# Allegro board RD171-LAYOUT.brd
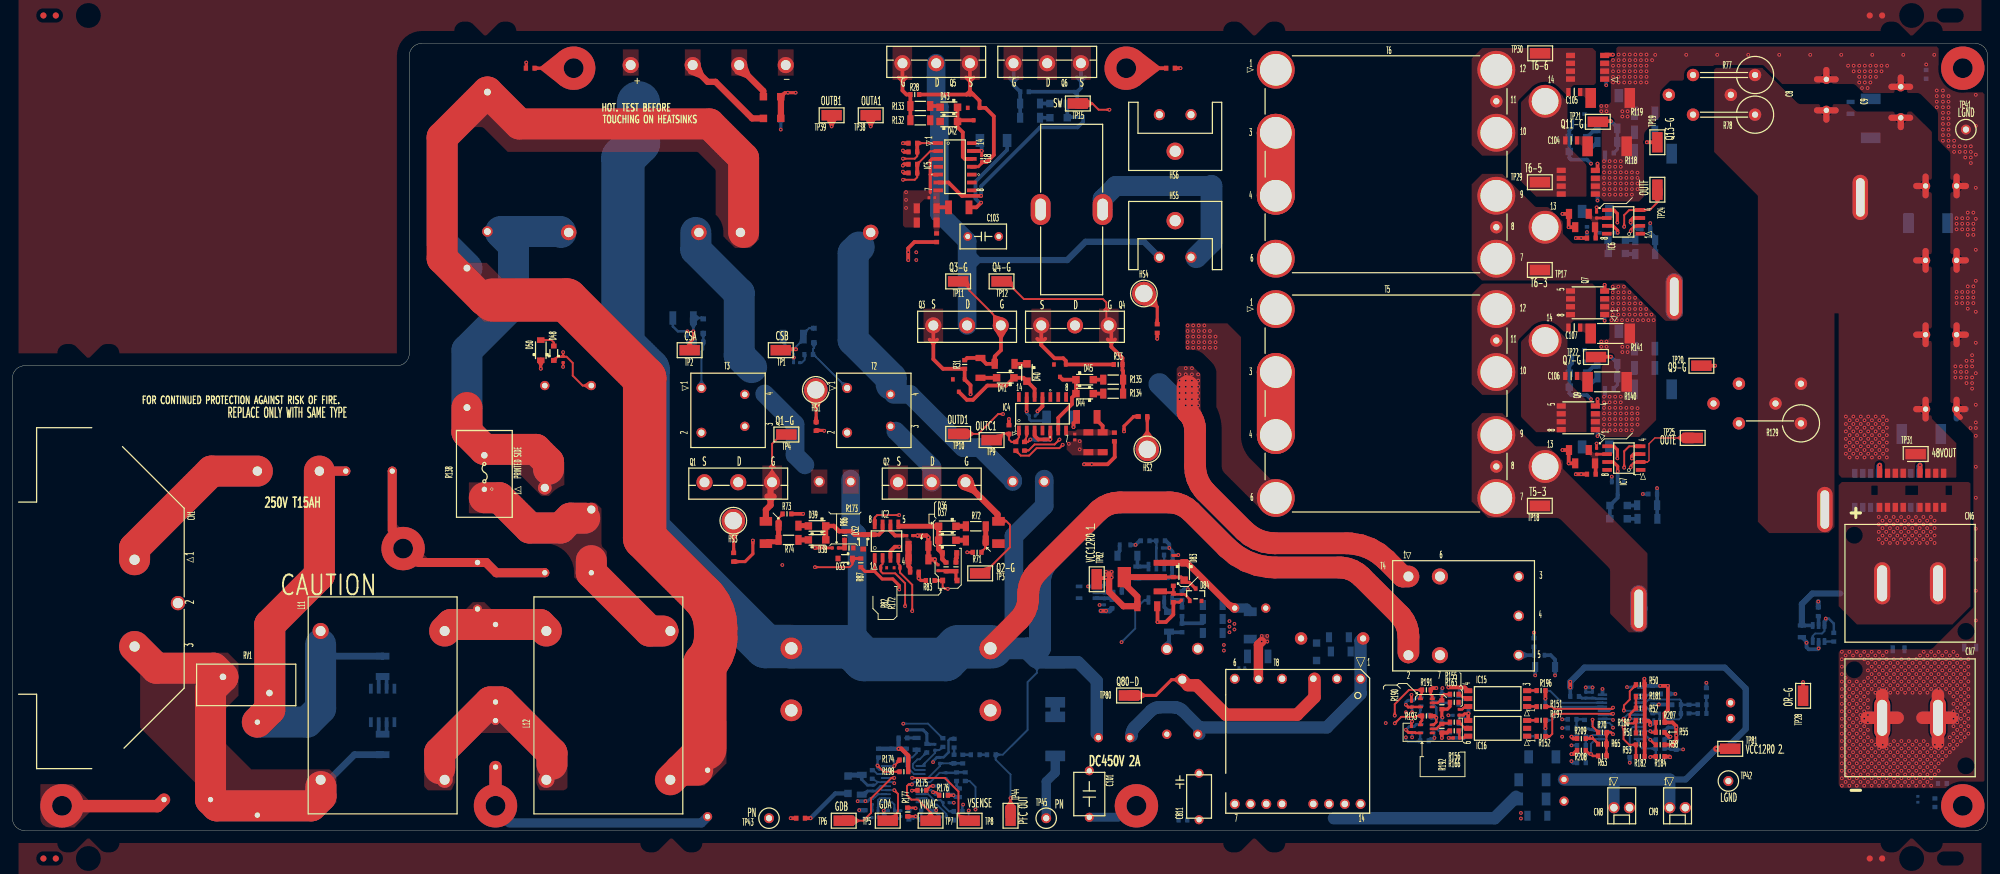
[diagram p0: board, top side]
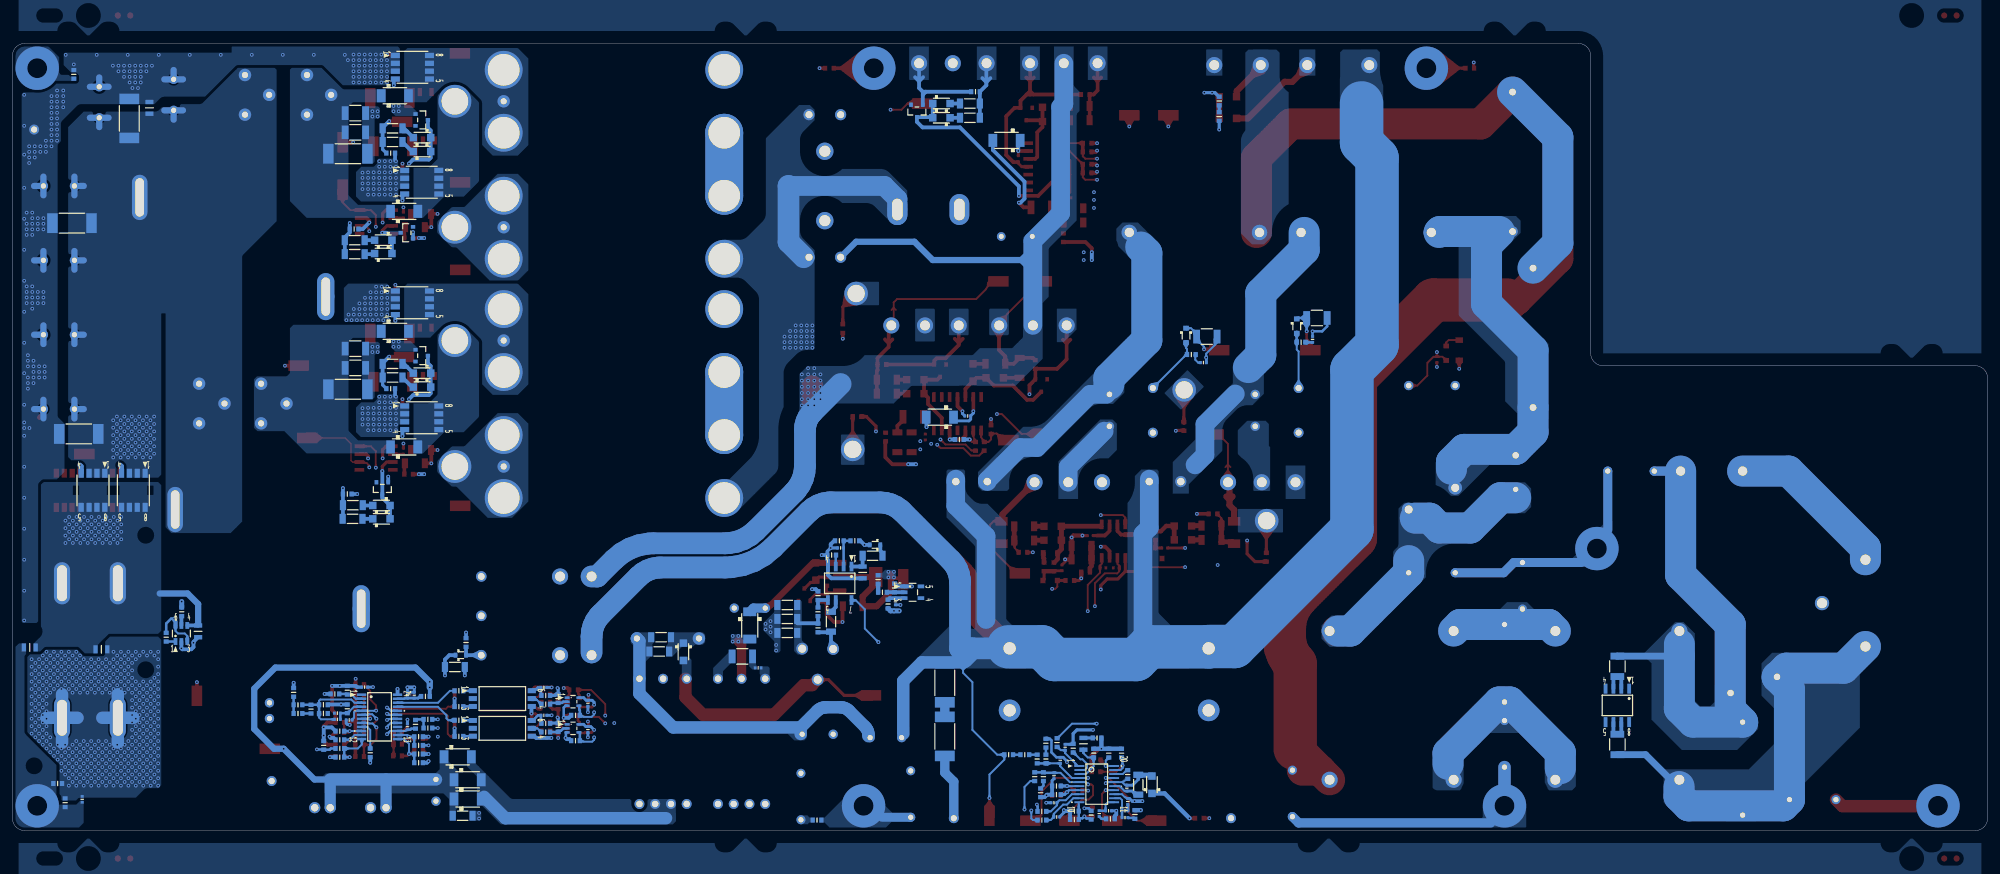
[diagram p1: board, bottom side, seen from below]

Outline 318.5 x 127 mm; copper layers: TOP, CONDUCTIVE2, CONDUCTIVE3, CONDUCTIVE4, CONDUCTIVE5, BOTTOM. Coordinates in mm from the lower left corner of the outline.
Outline path: 0,73 0.03,73.35 0.12,73.68 0.27,74 0.47,74.29 0.71,74.53 1,74.73 1.32,74.88 1.65,74.97 2,75 62,75 62.35,75.03 62.68,75.12 63,75.27 63.29,75.47 63.53,75.71 63.73,76 63.88,76.32 63.97,76.65 64,77 64,125 64.03,125.35 64.12,125.68 64.27,126 64.47,126.29 64.71,126.53 65,126.73 65.32,126.88 65.65,126.97 66,127 316.5,127 316.85,126.97 317.18,126.88 317.5,126.73 317.79,126.53 318.03,126.29 318.23,126 318.38,125.68 318.47,125.35 318.5,125 318.5,2 318.47,1.65 318.38,1.32 318.23,1 318.03,0.71 317.79,0.47 317.5,0.27 317.18,0.12 316.85,0.03 316.5,0 2,0 1.65,0.03 1.32,0.12 1,0.27 0.71,0.47 0.47,0.71 0.27,1 0.12,1.32 0.03,1.65 0,2 0,73

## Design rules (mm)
constraint set DEFAULT: 

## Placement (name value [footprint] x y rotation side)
C1  -  [AC_I_DIA_30_RB]  157.7 24.4 270 top
C2  -  [AC_I_DIA_10_CC]  311 104 0 top
C3  -  [AC_I_DIA_10_CC]  311 92 0 top
C4  -  [AC_I_DIA_10_CC]  311 80 0 top
C5  -  [AC_I_DIA_10_CC]  311 68 0 top
C7  -  [AC_I_DIA_30_RB]  125.6 24.4 270 top
C8  -  [AC_I_DIA_10_CC]  292.5 118.7 90 top
C9  -  [AC_I_DIA_10_CC]  304.5 117.5 90 top
C18  -  [CHIP1005_GS_2]  156.3 108.4 90 top
C19  -  [CHIP1005_GS_2]  164.45 66.9 180 bottom
C20  -  [CHIP1608_GS_1]  270.35 19.6 270 bottom
C21  -  [CHIP1005_GS_2]  266.1 18.95 180 bottom
C22  -  [CHIP1005_GS_2]  266.1 17.95 180 bottom
C23  -  [CHIP1005_GS_2]  253.7 21.85 270 bottom
C24  -  [CHIP1005_GS_2]  254.8 21.85 270 bottom
C25  -  [CHIP1005_GS_2]  264.2 17.85 180 bottom
C26  -  [CHIP1005_GS_2]  254.8 16.75 270 bottom
C27  -  [CHIP3225_GS_1]  263.2 115.75 0 bottom
C30  -  [C_I_LE474_M_OK]  39.5 10 90 top
C31  -  [C_I_DE2_KY____M_F_MU_1]  77.9 14 90 top
C32  -  [C_I_DE2_KY____M_F_MU_1]  75 39.5 270 top
C33  -  [C_I_890324026034CS_W_1]  76.6 107.9 270 top
C34  -  [CHIP1005_GS_2]  126.45 75.5 0 bottom
C35  -  [CHIP1005_GS_2]  149.25 42.4 270 top
C36  -  [CHIP1005_GS_2]  108.85 79.25 270 bottom
C37  -  [CHIP1005_GS_2]  132.7 45.6 0 top
C38  -  [CHIP1005_GS_2]  150.55 8.85 90 bottom
C39  -  [CHIP1005_GS_2]  149.55 11.35 270 bottom
C40  -  [CHIP1608_GS_1]  144.15 12.5 270 bottom
C41  -  [CHIP2012_GS_1]  145.8 14 270 bottom
C42  -  [CHIP1005_GS_2]  138.65 4.7 90 bottom
C43  -  [CHIP1005_GS_2]  139.1 3.2 0 bottom
C44  -  [CHIP1005_GS_2]  139.1 2.1 0 bottom
C45  -  [CHIP1005_GS_2]  141.75 3.2 0 bottom
C46  -  [CHIP1005_GS_2]  143.25 2.75 90 bottom
C47  -  [CHIP1005_GS_2]  138.8 6.85 270 bottom
C48  -  [CHIP3216_GS_1]  136.95 7.4 270 bottom
C49  -  [CHIP1608_GS_1]  138.65 9.05 90 bottom
C50  -  [CHIP1005_GS_2]  148.75 13.45 270 bottom
C51  -  [CHIP3225_GS_1]  263.2 77.75 0 bottom
C52  -  [C_I_LE224_M_OK]  77.9 27 90 top
C53  -  [CHIP1608_GS_1]  145.2 107.5 0 top
C54  -  [CHIP1608_GS_1]  145.2 110.9 0 top
C55  -  [CHIP1005_GS_2]  148.28 102.1 0 top
C56  -  [CHIP1608_GS_1]  165.8 63.1 180 bottom
C57  -  [CHIP1608_GS_1]  160.7 64.7 270 top
C58  -  [CHIP1005_GS_2]  171.3 63.5 90 top
C59  -  [CHIP1608_GS_1]  293.7 31.2 90 bottom
C60  -  [CHIP1005_GS_2]  255.45 61.2 270 top
C61  -  [CHIP1005_GS_2]  255.45 99.3 270 top
C62  -  [CHIP1005_GS_2]  144.7 47.6 180 top
C63  -  [C_I_DE2_KY____M_F_MU_1]  112.1 6 90 top
C64  -  [C_I_DE2_KY____M_F_MU_1]  89.6 41.6 0 top
C65  -  [C_I_890324026034CS_W_1]  73.3 79.5 270 top
C66  -  [CHIP1608_GS_1]  176.25 39.15 270 bottom
C67  -  [CHIP1005_GS_2]  176.1 36.9 90 bottom
C68  -  [CHIP3225_GS_1]  263.2 112.65 0 bottom
C69  -  [CHIP3225_GS_1]  263.2 74.65 0 bottom
C70  -  [CHIP1005_GS_2]  88.8 76 90 top
C71  -  [CHIP1005_GS_2]  232.8 23.1 0 bottom
C72  -  [CHIP1005_GS_2]  232.8 18.6 0 bottom
C73  -  [CHIP1005_GS_2]  233.3 19.1 90 top
C74  -  [CHIP1005_GS_2]  232.85 14.95 0 top
C75  -  [CHIP1005_GS_2]  150.55 4.5 180 bottom
C76  -  [CHIP1005_GS_2]  150.1 2.2 0 bottom
C77  -  [CHIP1608_GS_1]  147.25 3.15 180 bottom
C78  -  [C_I_DE2_KY____M_F_MU]  57.5 58 180 top
C79  -  [C_I_DE2_KY____M_F_MU]  28.2 5 0 top
C80  -  [CHIP1005_GS_2]  142.65 42.4 0 top
C81  -  [CHIP1005_GS_2]  140.5 42.4 180 top
C82  -  [CHIP3216_GS_1]  146.1 45.95 180 top
C83  -  [CHIP3216_GS_1]  146.1 43.75 180 top
C84  -  [CHIP3216_GS_1]  173.5 62.65 90 top
C85  -  [CHIP3216_GS_1]  175.8 62.65 90 top
C86  -  [CHIP3216_GS_1]  147.43 98.1 0 top
C87  -  [CHIP3216_GS_1]  147.43 100.4 0 top
C88  -  [CHIP3216_GS_1]  252.6 99.5 0 top
C89  -  [CHIP3216_GS_1]  253.6 97.35 0 top
C90  -  [CHIP3216_GS_1]  253.6 59.25 0 top
C91  -  [CHIP3216_GS_1]  252.6 61.4 0 top
C92  -  [CHIP2012_GS_1]  304.15 29.25 0 bottom
C93  -  [CHIP2012_GS_1]  315.7 29.55 180 bottom
C94  -  [CHIP1005_GS_2]  307.25 5.05 270 bottom
C95  -  [CHIP1005_GS_2]  225.7 20.55 90 bottom
C96  -  [CHIP1005_GS_2]  225.7 16.3 90 bottom
C97  -  [CHIP1005_GS_2]  225.6 20.4 270 top
C98  -  [CHIP1005_GS_2]  225.6 16.3 270 top
C99  -  [CHIP1005_GS_2]  261.7 23.15 0 bottom
C100  -  [CHIP2012_GS_1]  288.55 32.15 90 bottom
C101  -  [C_I_DE2_KY____M_F_MU]  173.65 5.9 270 top
C102  -  [CHIP2012_GS_1]  296.4 116.6 270 bottom
C103  -  [C_I_RDER72J104_MU]  156.55 95.85 180 top
C104  -  [CHIP2012_GS_1]  251.35 111.35 180 top
C105  -  [CHIP2012_GS_1]  251.85 119.15 180 top
C106  -  [CHIP2012_GS_1]  251.35 73.35 180 top
C107  -  [CHIP2012_GS_1]  251.85 81.15 180 top
C800  -  [AC_I_DIA_10_CC_2]  188.65 15.55 180 top
C801  -  [CHIP3216_GS_1]  214.2 28.9 180 bottom
C802  -  [CHIP2012_GS_1]  181.4 41.65 90 bottom
C803  -  [CHIP1608_GS_1]  188.6 37.9 270 bottom
C804  -  [AC_I_DIA_10_CC_3]  199.6 35.9 0 top
C805  -  [CHIP1005_GS_2]  188.5 37.65 270 top
C806  -  [CHIP3216_GS_1]  183 36.2 0 top
C807  -  [CHIP3216_GS_1]  213.9 31.2 180 bottom
C808  -  [CHIP1005_GS_2]  187.15 43.92 90 top
C809  -  [AC_I_DIA_8_CC_1]  250.2 6.5 270 top
C810  -  [CHIP1005_GS_2]  198.25 26.25 180 bottom
C811  -  [C_I_DE1B3RA471_GS_1]  191.35 5.5 90 top
C812  -  [CHIP1005_GS_2]  184.95 45.6 180 bottom
CN1  -  [TM_I_AC_P05CP24_ED]  3.9 37.5 90 top
CN6  -  [TM_I_OP_910_GS]  306 39.9 90 top
CN7  -  [TM_I_OP_910_GS]  306 18.2 90 top
CN8  -  [CN_I_5045_02A_MX]  259.5 3.7 180 top
CN9  -  [CN_I_5045_02A_MX]  268.5 3.7 180 top
CN10  -  [HP_I_A2_2PA_2_54DSA__1]  277.05 19.35 90 top
D1  -  [DI_I_TO220F_2L_TS]  132.64 56.31 180 top
D2  -  [DI_I_TO220F_2L_TS]  163.84 56.31 180 top
D3  -  [DI_I_GSIB_5S_4_VS]  112.2 123.5 0 top
D8  -  [DI_S_3_2A1S_2_TS_A]  122.5 114.9 0 top
D9  -  [DI_S_3_2A1S_2_TS_A]  122.5 118.4 0 top
D12  -  [DI_S_USC_2_TS_B]  129.25 79.9 270 bottom
D13  -  [DI_S_USC_2_TS_B]  111.4 81.4 270 bottom
D14  -  [DI_S_1SS387_TS_B]  246.2 28.3 270 bottom
D16  -  [DI_S_3_4E1A_2_TS_B]  158.2 111.35 180 bottom
D17  -  [DI_S_3_4E1A_2_TS_B]  168.95 66.7 180 bottom
D18  -  [DI_I_TO220_2_KC]  187.5 115.5 180 top
D19  -  [DI_I_TO220_2_KC]  187.5 92.5 0 top
D20  -  [DI_S_3_4E1A_2_TS_B]  255.32 99.9 0 bottom
D21  -  [DI_S_3_4E1A_2_TS_B]  256.82 118.55 0 bottom
D22  -  [DI_S_SOT23_3_0_95_TS_1]  172.65 116.1 0 bottom
D23  -  [DI_S_SOT23_3_0_95_TS_1]  155 115.6 180 top
D24  -  [DI_S_SOT23_3_0_95_TS_1]  152.6 71.8 180 top
D25  -  [DI_S_SOT23_3_0_95_TS_1]  168.9 74.2 180 top
D26  -  [DI_S_SOT23_3_0_95_TS_1]  254.9 96.45 90 bottom
D27  -  [DI_S_SOT23_3_0_95_TS_1]  252.5 114.65 270 bottom
D28  -  [DI_S_SOT23_3_0_95_TS_1]  252.5 76.62 270 bottom
D29  -  [DI_S_SOT23_3_0_95_TS_1]  258.85 55.2 0 bottom
D30  -  [DI_S_USC_2_TS_B]  151.1 44.8 0 top
D31  -  [DI_S_USC_2_TS_B]  151.15 40.35 0 top
D32  -  [DI_S_USC_2_TS_B]  137.2 46.6 270 top
D33  -  [DI_S_USC_2_TS_B]  134.3 43.9 180 top
D34  -  [DI_S_3_4E1A_2_TS_B]  255.32 61.9 0 bottom
D35  -  [DI_S_3_4E1A_2_TS_B]  256.82 80.55 0 bottom
D36  -  [DI_S_CRS01_TS_B]  150.75 49.1 0 top
D37  -  [DI_S_CRS01_TS_B]  150.75 46.85 180 top
D38  -  [DI_S_CRS01_TS_B]  129.75 46.9 180 top
D39  -  [DI_S_CRS01_TS_B]  129.75 49.15 0 top
D40  -  [DI_S_CRS01_TS_B]  163.6 73.9 90 top
D41  -  [DI_S_CRS01_TS_B]  160.1 73.05 0 top
D42  -  [DI_S_CRS01_TS_B]  151 114.4 180 top
D43  -  [DI_S_CRS01_TS_B]  151 116.7 0 top
D44  -  [DI_S_CRS01_TS_B]  172.9 70.5 0 top
D45  -  [DI_S_CRS01_TS_B]  172.9 72.75 180 top
D46  -  [DI_S_CRS01_TS_B]  168.7 115 180 bottom
D47  -  [DI_S_CRS01_TS_B]  168.7 117.3 0 bottom
D48  -  [DI_S_USC_2_TS_B]  87.3 77 90 top
D49  -  [DI_S_3_2A1S_2_TS_A]  134.75 7.4 270 bottom
D50  -  [DI_S_SOD_123_2_OS_A]  85.2 77.5 270 top
D51  -  [DI_S_CRS01_TS_B]  252.45 109.55 0 bottom
D52  -  [DI_S_CRS01_TS_B]  252.45 111.8 180 bottom
D53  -  [DI_S_CRS01_TS_B]  258.7 93.1 0 bottom
D54  -  [DI_S_CRS01_TS_B]  258.7 95.25 180 bottom
D55  -  [DI_S_CRS01_TS_B]  252.45 71.55 0 bottom
D56  -  [DI_S_CRS01_TS_B]  252.45 73.8 180 bottom
D57  -  [DI_S_CRS01_TS_B]  259 50.3 0 bottom
D58  -  [DI_S_CRS01_TS_B]  259 52.45 180 bottom
D80  -  [DI_S_3_2A1S_2_TS_A]  210.3 28.85 90 bottom
D81  -  [DI_S_1SS387_TS_B]  179.4 46.1 90 bottom
D82  -  [DI_S_3_4E1A_2_TS_B]  199.6 33.1 90 bottom
D83  -  [DI_S_CRS01_TS_B]  188.95 41.8 90 top
D84  -  [DI_S_SOT23_3_0_95_TS_1]  190.8 38.05 0 top
D90  -  [DI_S_3_4E1A_2_TS_B]  245.1 5.1 0 bottom
D91  -  [DI_S_3_4E1A_2_TS_B]  245.1 8.2 0 bottom
D92  -  [DI_S_3_4E1A_2_TS_B]  246.7 11.9 0 bottom
F1  -  [F_I_02150__XEP_LF]  39.5 58 0 top
F8  -  [F_I_808__0440_LF]  177.65 15 0 top
FB1  -  [FB_S_FBMH3216_TY]  159 48.1 90 top
FB2  -  [FB_S_FBMH3216_TY]  121.5 48.1 90 top
HS1  -  [TP_I_TH2_8_TBLC3_8_I_1]  129.55 71.1 0 top
HS2  -  [TP_I_TH2_8_TBLC3_8_I_1]  183 61.5 0 top
HS3  -  [TP_I_TH2_8_TBLC3_8_I_1]  116.25 50 0 top
HS4  -  [TP_I_TH2_8_TBLC3_8_I_1]  182.45 86.65 0 top
HS5  -  [HS_I_BPUS15_25_GS]  187.5 95.5 0 top
HS6  -  [HS_I_BPUS15_25_GS]  187.5 112.5 180 top
IC1  -  [IC_S_SOP_8_1_27_MPS]  59.7 20.2 0 bottom
IC2  -  [IC_S_SOP_8_1_27_TI]  140.95 46.7 0 top
IC3  -  [IC_S_SOP_20_0_65_TI]  143.65 7.5 270 bottom
IC4  -  [IC_S_SOP_14_1_27_TI]  166.1 67.25 0 top
IC5  -  [IC_S_SOP_14_1_27_TI]  152 107.1 270 top
IC6  -  [IC_S_SOP_8_1_27_TI]  259.8 98.2 90 top
IC7  -  [IC_S_SOP_8_1_27_TI]  259.85 60.1 90 top
IC8  -  [IC_S_SOP_6_0_95_TI]  291.25 31.8 180 bottom
IC10  -  [IC_S_SOP_24_0_65_GS__1]  259.3 18.35 270 bottom
IC11  -  [IC_S_SOP_5_0_95_TI]  173.35 38.45 270 bottom
IC13  -  [PH_S_TLP2767_TS]  239.5 21.3 270 bottom
IC14  -  [PH_S_TLP2767_TS]  239.5 16.5 270 bottom
IC15  -  [PH_S_TLP2767_TS]  239.5 21.3 90 top
IC16  -  [PH_S_TLP2767_TS]  239.5 16.5 90 top
IC20  -  [RE_I_ALKG_2__PN]  89.6 61.45 270 top
IC21  -  [IC_S_SOP_5_0_65_TS_1]  228.1 20.8 270 bottom
IC22  -  [IC_S_SOP_5_0_65_TS_1]  228.1 16.5 270 bottom
IC23  -  [IC_S_SOP_5_0_65_TS_1]  228 20.6 90 top
IC24  -  [IC_S_SOP_5_0_65_TS_1]  228 16.4 90 top
IC80  -  [IC_S_SOP_7_1_27_TI]  185.1 39.9 0 bottom
IC81  -  [IC_S_SOT223_3_2_3_TI]  185.1 40.9 90 top
L1  -  [L_I_TH23_14V_08231_T_1]  100.2 96.5 270 top
L2  -  [L_I_TH23_14V_08231_T_1]  127.9 96.5 270 top
L3  -  [L_I_NPA080_13X2_20T__1]  170.8 100.2 270 top
L5  -  [L_I_AG1391_GS]  277.25 43.8 270 top
L6  -  [L_I_AG1391_GS]  282.98 94.15 270 top
L11  -  [L_I_SCF27_10_1300_TN]  59.7 20.2 270 top
L12  -  [L_I_SCF27_10_1300_TN]  96.1 20.2 270 top
NOREF  -  []  15.7 63.7 180 top
NOREF#2  -  []  12.65 17.45 0 top
NOREF#3  -  []  297 25.95 0 top
NOREF#4  -  []  12.65 57.55 0 top
NOREF#5  -  []  315 10.45 0 top
NOREF#6  -  []  306.25 -4.5 0 top
NOREF#7  -  []  12.25 131.5 0 top
NOREF#8  -  []  12.25 -4.5 0 top
NOREF#9  -  [unnamed#2]  5 131.5 0 top
NOREF#10  -  []  225.05 3.65 0 top
NOREF#11  -  []  306.25 131.5 0 top
NOREF#12  -  []  15.7 11.3 180 top
NOREF#13  -  []  8 71 0 top
NOREF#14  -  []  297 47.65 0 top
NOREF#15  -  []  102.4 -25.8 0 top
NOREF#16  -  [unnamed#2]  301.5 -4.5 180 top
NOREF#17  -  [unnamed#2]  301.5 131.5 180 top
NOREF#18  -  [unnamed#2]  5 -4.5 0 top
NOREF#19  -  []  130.6 -20.1 0 top
NOREF#20  -  []  315 32.15 0 top
Q1  -  [TR_I_TO247_3_TS]  117.04 56.2 180 top
Q2  -  [TR_I_TO247_3_TS]  148.24 56.2 180 top
Q3  -  [TR_I_TO247_3_TS]  153.94 81.5 180 top
Q4  -  [TR_I_TO247_3_TS]  171.34 81.5 180 top
Q5  -  [TR_I_TO247_3_TS]  148.96 123.8 0 top
Q6  -  [TR_I_TO247_3_TS]  166.86 123.8 0 top
Q7  -  [TR_S_SOP_ADVANCE_TS]  254 85.15 90 top
Q8  -  [TR_S_SOP_ADVANCE_TS]  254 85.15 270 bottom
Q9  -  [TR_S_SOP_ADVANCE_TS]  252.5 66.6 90 top
Q10  -  [TR_S_SOP_ADVANCE_TS]  252.5 66.6 270 bottom
Q11  -  [TR_S_SOP_ADVANCE_TS]  254 123.15 90 top
Q12  -  [TR_S_SOP_ADVANCE_TS]  254 123.15 270 bottom
Q13  -  [TR_S_SOP_ADVANCE_TS]  252.5 104.6 90 top
Q14  -  [TR_S_SOP_ADVANCE_TS]  252.5 104.6 270 bottom
Q15  -  [TR_S_SOP_ADVANCE_TS]  309.5 54.9 180 top
Q16  -  [TR_S_SOP_ADVANCE_TS]  303 54.9 180 top
Q17  -  [TR_S_SOP_ADVANCE_TS]  299 54.9 0 bottom
Q18  -  [TR_S_SOP_ADVANCE_TS]  305.5 54.9 0 bottom
Q80  -  [TR_I_TO220SIS_TS_1]  188.65 29.35 0 top
R1  -  [CHIP1608_GS_1]  153.65 8.7 270 bottom
R2  -  [CHIP1608_GS_1]  152.7 6.1 90 bottom
R6  -  [CHIP1608_GS_1]  291.2 35.3 90 bottom
R7  -  [CHIP3225_GS_1]  108.15 82.7 0 bottom
R8  -  [CHIP3225_GS_1]  125.9 79.7 0 bottom
R9  -  [CHIP1608_GS_1]  245.35 30.35 270 bottom
R18  -  [CHIP3216_GS_1]  257.2 111.1 0 bottom
R19  -  [CHIP1608_GS_1]  257.5 109.3 0 bottom
R20  -  [CHIP3216_GS_1]  263.3 93 0 bottom
R21  -  [CHIP1608_GS_1]  263.4 97.05 0 bottom
R22  -  [CHIP1608_GS_1]  257.5 71.3 0 bottom
R23  -  [CHIP3216_GS_1]  257.2 73.1 0 bottom
R24  -  [CHIP3216_GS_1]  263.65 50.3 0 bottom
R25  -  [CHIP1608_GS_1]  264.5 54.3 0 bottom
R28  -  [CHIP1608_GS_1]  145.5 118.75 180 top
R29  -  [CHIP1608_GS_1]  163.2 119.2 180 bottom
R31  -  [CHIP1608_GS_1]  153.55 75.2 90 top
R33  -  [CHIP1608_GS_1]  178.3 75.2 0 top
R42  -  [CHIP1608_GS_1]  272.45 20.3 0 bottom
R43  -  [CHIP1608_GS_1]  268.35 20.3 0 bottom
R44  -  [CHIP1608_GS_1]  264.5 22.65 90 bottom
R45  -  [CHIP1608_GS_1]  266.5 22.05 180 bottom
R46  -  [CHIP1608_GS_1]  272.45 18.9 0 bottom
R47  -  [CHIP1608_GS_1]  268.35 18.9 0 bottom
R48  -  [CHIP1608_GS_1]  264.5 19.65 270 bottom
R49  -  [CHIP1608_GS_1]  251.9 21.65 0 bottom
R50  -  [CHIP1608_GS_1]  262.5 23.55 180 top
R51  -  [CHIP1608_GS_1]  262.5 15.75 180 top
R52  -  [CHIP1608_GS_1]  262.5 19.75 180 top
R53  -  [CHIP1608_GS_1]  262.5 13.85 180 top
R54  -  [CHIP1608_GS_1]  260.8 12.55 90 bottom
R55  -  [CHIP1608_GS_1]  265.7 15.85 180 top
R56  -  [CHIP1608_GS_1]  265.7 14.65 180 bottom
R57  -  [CHIP1608_GS_1]  265.7 16.05 0 bottom
R58  -  [CHIP1608_GS_1]  265.7 13.85 0 top
R59  -  [CHIP1608_GS_1]  251.5 17.95 0 bottom
R60  -  [CHIP1608_GS_1]  265.7 13.25 0 bottom
R61  -  [CHIP1608_GS_1]  265.7 11.85 180 bottom
R62  -  [CHIP1608_GS_1]  268.3 13.75 90 bottom
R63  -  [CHIP1608_GS_1]  256.4 12.05 0 top
R64  -  [CHIP1608_GS_1]  253 12.35 0 bottom
R65  -  [CHIP1608_GS_1]  256.4 13.95 0 top
R66  -  [CHIP1608_GS_1]  253 15.15 0 bottom
R67  -  [CHIP1608_GS_1]  251.5 16.55 180 bottom
R69  -  [CHIP1608_GS_1]  253.5 17.15 90 bottom
R70  -  [CHIP1608_GS_1]  256.4 15.85 0 top
R71  -  [CHIP1608_GS_1]  155.55 44.9 0 top
R72  -  [CHIP3216_GS_1]  155.35 49.1 0 top
R73  -  [CHIP1608_GS_1]  124.9 51.1 180 top
R74  -  [CHIP3216_GS_1]  125.15 46.9 180 top
R75  -  [CHIP1608_GS_1]  273.15 22.3 90 bottom
R76  -  [CHIP6432_GS]  264.4 109.2 0 bottom
R77  -  [R_I_MOS3C_KO]  281 121.9 180 top
R78  -  [R_I_MOS3C_KO]  281 115.5 180 top
R79  -  [CHIP3225_GS_1]  59.7 26.5 90 bottom
R80  -  [CHIP3225_GS_1]  59.7 13.9 90 bottom
R81  -  [CHIP1608_GS_1]  128.4 76.8 0 bottom
R82  -  [CHIP1608_GS_1]  150.55 42.55 270 top
R83  -  [CHIP1608_GS_1]  148 40.35 180 top
R85  -  [CHIP1608_GS_1]  110.7 78.8 0 bottom
R86  -  [CHIP1608_GS_1]  134.2 47.6 270 top
R87  -  [CHIP1608_GS_1]  136.8 43.2 270 top
R89  -  [CHIP1608_GS_1]  153.25 11.55 90 bottom
R90  -  [CHIP1608_GS_1]  151.85 14.1 270 bottom
R91  -  [CHIP1608_GS_1]  155.25 12.25 0 bottom
R92  -  [CHIP1608_GS_1]  157.85 12.25 0 bottom
R93  -  [CHIP1608_GS_1]  143.6 14.95 0 bottom
R94  -  [CHIP1608_GS_1]  123.9 115.2 90 bottom
R95  -  [CHIP1608_GS_1]  123.9 117.7 90 bottom
R96  -  [CHIP1608_GS_1]  147.25 1.8 180 bottom
R97  -  [CHIP1608_GS_1]  144.55 2.5 90 bottom
R98  -  [CHIP1608_GS_1]  137.5 2.6 270 bottom
R99  -  [CHIP1608_GS_1]  141.45 1.9 0 bottom
R100  -  [CHIP1608_GS_1]  139.65 12.5 270 bottom
R101  -  [CHIP1608_GS_1]  150.15 5.8 180 bottom
R102  -  [CHIP1608_GS_1]  150.15 7.2 180 bottom
R103  -  [CHIP1608_GS_1]  141.7 12.5 270 bottom
R104  -  [CHIP1608_GS_1]  147.45 13.3 270 bottom
R105  -  [CHIP6432_GS]  264.4 71.2 0 bottom
R106  -  [R_I_MOS3C_KO]  288.4 72.1 180 top
R107  -  [R_I_MOS3C_KO]  274.3 68.9 0 top
R108  -  [CHIP3216_GS_1]  155.35 46.8 0 top
R109  -  [CHIP3216_GS_1]  125.15 49.2 180 top
R110  -  [CHIP1608_GS_1]  145.2 106.1 0 top
R111  -  [CHIP1608_GS_1]  145.2 109.5 0 top
R112  -  [CHIP1608_GS_1]  163.2 62 90 top
R113  -  [CHIP1608_GS_1]  161.8 62 90 top
R114  -  [CHIP3225_GS_1]  152.6 100.55 0 top
R115  -  [CHIP3225_GS_1]  173.25 66.75 180 top
R116  -  [CHIP1608_GS_1]  178.9 40.5 270 bottom
R117  -  [CHIP1608_GS_1]  177.3 36.55 270 bottom
R118  -  [CHIP6432_GS]  257.15 110.4 180 top
R119  -  [CHIP6432_GS]  257.65 118.2 180 top
R120  -  [CHIP1608_GS_1]  127.1 2 0 top
R121  -  [CHIP1608_GS_1]  145.45 41.7 180 top
R122  -  [CHIP1608_GS_1]  177.7 63.5 90 top
R123  -  [CHIP1608_GS_1]  149.03 95.65 90 top
R124  -  [CHIP1608_GS_1]  254.6 57.5 0 top
R125  -  [CHIP1608_GS_1]  254.6 95.6 0 top
R126  -  [CHIP3216_GS_1]  160 75.3 180 top
R127  -  [CHIP3216_GS_1]  156.1 74.65 90 top
R128  -  [R_I_MOS3C_KO]  267.1 118.7 0 top
R129  -  [R_I_MOS3C_KO]  288.4 65.7 180 top
R130  -  [CHIP1608_GS_1]  178.2 38.45 180 bottom
R132  -  [CHIP3216_GS_1]  146.4 114.6 180 top
R133  -  [CHIP3216_GS_1]  146.4 116.9 180 top
R134  -  [CHIP3216_GS_1]  177.5 70.5 0 top
R135  -  [CHIP3216_GS_1]  177.5 72.75 0 top
R136  -  [CHIP3216_GS_1]  164.1 115 180 bottom
R137  -  [CHIP3216_GS_1]  164.1 117.3 180 bottom
R138  -  [F_I_A5MC_UC]  76.1 57.8 90 top
R140  -  [CHIP6432_GS]  257.15 72.4 180 top
R141  -  [CHIP6432_GS]  257.65 80.2 180 top
R149  -  [CHIP1608_GS_1]  246.5 22.55 0 bottom
R150  -  [CHIP1608_GS_1]  246.5 17.8 0 bottom
R151  -  [CHIP1608_GS_1]  246.5 20 0 top
R152  -  [CHIP1608_GS_1]  246.5 15.2 0 top
R153  -  [CHIP1608_GS_1]  232.5 20.4 0 bottom
R154  -  [CHIP1608_GS_1]  232.5 15.9 0 bottom
R155  -  [CHIP1608_GS_1]  232.5 22 0 top
R156  -  [CHIP1608_GS_1]  232.5 17.5 0 top
R157  -  [CHIP1608_GS_1]  232.5 21.8 0 bottom
R160  -  [CHIP1608_GS_1]  232.5 17.3 0 bottom
R163  -  [CHIP1608_GS_1]  232.5 20.7 0 top
R166  -  [CHIP1608_GS_1]  232.5 16.1 0 top
R169  -  [CHIP1608_GS_1]  152.5 3.1 180 bottom
R170  -  [CHIP1608_GS_1]  152.5 1.7 180 bottom
R171  -  [CHIP1608_GS_1]  150.05 14.2 90 bottom
R172  -  [CHIP1608_GS_1]  152.15 42.55 270 top
R173  -  [CHIP1608_GS_1]  134.9 45.6 180 top
R174  -  [CHIP1608_GS_1]  143.75 11.4 180 top
R175  -  [CHIP1608_GS_1]  146.65 6.5 0 top
R176  -  [CHIP1608_GS_1]  150.15 5.7 180 top
R177  -  [CHIP1608_GS_1]  144.35 3 90 top
R178  -  [CHIP6432_GS]  168.15 23.85 90 bottom
R179  -  [CHIP6432_GS]  168.15 15.2 90 bottom
R180  -  [CHIP1608_GS_1]  262.5 17.75 180 top
R181  -  [CHIP1608_GS_1]  262.5 21.65 180 top
R182  -  [CHIP1608_GS_1]  262.5 11.95 180 top
R184  -  [CHIP1608_GS_1]  265.7 11.95 180 top
R185  -  [CHIP3216_GS_1]  247.15 26.4 0 bottom
R186  -  [CHIP1608_GS_1]  230.5 21.3 90 bottom
R187  -  [CHIP1608_GS_1]  227.7 18.6 180 bottom
R188  -  [CHIP1608_GS_1]  230.5 16.65 90 bottom
R189  -  [CHIP1608_GS_1]  227.7 14.5 180 bottom
R190  -  [CHIP1608_GS_1]  230.5 20.3 270 top
R191  -  [CHIP1608_GS_1]  228 22.7 180 top
R192  -  [CHIP1608_GS_1]  230.5 16.5 270 top
R193  -  [CHIP1608_GS_1]  228 18.5 180 top
R194  -  [CHIP1608_GS_1]  246.5 20 0 bottom
R195  -  [CHIP1608_GS_1]  246.5 15.2 0 bottom
R196  -  [CHIP1608_GS_1]  246.5 22.6 0 top
R197  -  [CHIP1608_GS_1]  246.5 17.8 0 top
R198  -  [CHIP1608_GS_1]  143.75 9.5 180 top
R199  -  [CHIP6432_GS]  307.8 64 180 bottom
R200  -  [CHIP6432_GS]  299.65 114.9 270 bottom
R201  -  [CHIP6432_GS]  308.9 98 180 bottom
R204  -  [CHIP1608_GS_1]  308.6 122 90 bottom
R205  -  [CHIP1608_GS_1]  311.2 7.6 180 bottom
R206  -  [CHIP1608_GS_1]  310 4.5 90 bottom
R207  -  [CHIP1608_GS_1]  265.7 17.45 0 top
R208  -  [CHIP1608_GS_1]  253 12.95 0 top
R209  -  [CHIP1608_GS_1]  253 14.85 0 top
R210  -  [CHIP1608_GS_1]  253 10.95 180 bottom
R211  -  [CHIP1608_GS_1]  253 13.75 180 bottom
R212  -  [CHIP3216_GS_1]  257.2 113.3 0 bottom
R213  -  [CHIP3216_GS_1]  263.3 95.25 0 bottom
R214  -  [CHIP3216_GS_1]  257.2 75.3 0 bottom
R215  -  [CHIP3216_GS_1]  263.6 52.5 0 bottom
R220  -  [CHIP1608_GS_1]  129.6 65.2 90 top
R221  -  [CHIP1608_GS_1]  182.3 66.8 0 top
R222  -  [CHIP1608_GS_1]  116.3 44.1 90 top
R223  -  [CHIP1608_GS_1]  184.6 81 90 top
R224  -  [CHIP1608_GS_1]  186.75 123 180 top
R225  -  [CHIP1608_GS_1]  83.5 123 0 top
R227  -  [CHIP1608_GS_1]  151.85 11.55 270 bottom
R228  -  [CHIP1608_GS_1]  152.25 8.7 90 bottom
R800  -  [R_I_MOS3C_KO]  207.8 31 0 top
R801  -  [CHIP3225_GS_1]  200.8 28.1 0 bottom
R802  -  [CHIP3216_GS_1]  186.5 33.7 270 bottom
R803  -  [CHIP1608_GS_1]  188.6 32.7 270 bottom
R804  -  [CHIP1608_GS_1]  188.6 35.3 270 bottom
R805  -  [CHIP1608_GS_1]  188.75 1.7 180 bottom
R806  -  [CHIP3216_GS_1]  179.8 44.35 0 bottom
R807  -  [CHIP1608_GS_1]  186.4 44.45 180 bottom
R808  -  [CHIP1608_GS_1]  182.65 46.75 180 bottom
R809  -  [CHIP1608_GS_1]  185.15 46.75 180 bottom
R810  -  [CHIP1608_GS_1]  187.2 40.2 270 top
R811  -  [CHIP1608_GS_1]  187.2 37.55 270 top
R812  -  [CHIP3216_GS_1]  193.55 31.9 180 bottom
R813  -  [CHIP3216_GS_1]  193.55 34.15 180 bottom
R814  -  [CHIP3216_GS_1]  193.55 36.4 180 bottom
R820  -  [CHIP3216_GS_1]  245.9 2.4 0 bottom
RV1  -  [ZD_I_TND14V_561_CC]  37.7 23.5 0 top
T2  -  [T_I_P009_203_PO]  138.1 67.8 270 top
T3  -  [T_I_P009_203_PO]  114.6 67.8 270 top
T4  -  [T_I_PE_63587NL_PU]  234 34.65 0 top
T5  -  [T_I_AN0545_GS]  221.5 68.9 0 top
T6  -  [T_I_AN0545_GS]  221.5 107.5 0 top
T8  -  [T_I_WT2020_GS]  207.25 14.4 270 top
TP1  -  [TP_S_HK_2_M8]  123.9 77.5 0 top
TP2  -  [TP_S_HK_2_M8]  109.2 77.5 0 top
TP3  -  [TP_S_HK_2_M8]  156.05 41.5 0 top
TP4  -  [TP_S_HK_2_M8]  124.8 63.9 0 top
TP5  -  [TP_S_HK_2_M8]  141.15 1.6 0 top
TP6  -  [TP_S_HK_2_M8]  134.05 1.6 0 top
TP7  -  [TP_S_HK_2_M8]  148.05 1.6 0 top
TP8  -  [TP_S_HK_2_M8]  154.35 1.6 0 top
TP9  -  [TP_S_HK_2_M8]  157.9 63 0 top
TP10  -  [TP_S_HK_2_M8]  152.5 64 0 top
TP11  -  [TP_S_HK_2_M8]  152.5 88.6 0 top
TP12  -  [TP_S_HK_2_M8]  159.5 88.6 0 top
TP15  -  [TP_S_HK_2_M8]  171.8 117.3 0 top
TP17  -  [TP_S_HK_2_M8]  246.3 90.45 0 top
TP18  -  [TP_S_HK_2_M8]  246.3 52.4 0 top
TP19  -  [TP_S_HK_2_M8]  265.25 111.05 270 top
TP20  -  [TP_S_HK_2_M8]  272.35 75 0 top
TP21  -  [TP_S_HK_2_M8]  255.65 114.35 0 top
TP22  -  [TP_S_HK_2_M8]  255.35 76.4 0 top
TP24  -  [TP_S_HK_2_M8]  265.25 103.4 90 top
TP25  -  [TP_S_HK_2_M8]  270.95 63.35 0 top
TP28  -  [TP_S_HK_2_M8]  288.75 21.75 90 top
TP29  -  [TP_S_HK_2_M8]  246.3 104.6 0 top
TP30  -  [TP_S_HK_2_M8]  246.35 125.4 0 top
TP31  -  [TP_S_HK_2_M8]  306.9 60.75 180 top
TP38  -  [TP_S_HK_2_M8]  138.4 115.4 0 top
TP39  -  [TP_S_HK_2_M8]  132.1 115.4 0 top
TP41  -  [TP_I_LC_22_GS]  315 113.1 0 top
TP42  -  [TP_I_LC_22_GS]  276.7 8 0 top
TP43  -  [TP_I_LC_22_GS]  122 2 0 top
TP44  -  [TP_S_HK_2_M8]  160.95 2.4 90 top
TP45  -  [TP_I_LC_22_GS]  166.7 2 0 top
TP80  -  [TP_S_HK_2_M8]  180.05 21.8 180 top
TP81  -  [TP_S_HK_2_M8]  277 13.2 0 top
TP82  -  [TP_S_HK_2_M8]  174.85 40.55 90 top

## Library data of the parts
C1 C7 = 450MXK330MEFCSN30X30_RB
C2-C5 C8 C9 = EKZN630ELL331MJ25S_CC
C18 C19 C21-C26 C34-C39 C42-C47 C50 C55 C58 C60-C62 C67 C70-C76 C80 C81 C94-C99 C805 C808 C810 C812 = Chip1005_GS_2
C20 C40 C49 C53 C54 C56 C57 C59 C66 C77 C803 R1 R2 R6 R9 R19 R21 R22 R25 R28 R29 R31 R33 R42-R67 R69-R71 R73 R75 R81-R83 R85-R87 R89-R104 R110-R113 R116 R117 R120-R125 R130 R149-R157 R160 R163 R166 R169-R177 R180-R182 R184 R186-R198 R204-R211 R220-R225 R227 R228 R803-R805 R807-R811 = Chip1608_GS_1
C27 C51 C68 C69 R7 R8 R79 R80 R114 R115 R801 = Chip3225_GS_1
C30 = LE474-M_OK
C31 C32 C63 C64 = DE2E3KY222MN3AM02F_MU
C33 C65 = 890324026034CS_WE
C41 C92 C93 C100 C102 C104-C107 C802 = Chip2012_GS_1
C48 C82-C91 C801 C806 C807 R18 R20 R23 R24 R72 R74 R108 R109 R126 R127 R132-R137 R185 R212-R215 R802 R806 R812-R814 R820 = Chip3216_GS_1
C52 = LE224-M_OK
C78 C79 = DE2B3KY101KA3BM02F_MU
C101 = DE2B3KY221KA3BM02F_MU
C103 = RDER72J104_MU
C800 = EKXJ451E**6R8MJ16S_CC_2
C804 = EKZH350E**331MJC5S_CC_3
C809 = EKZH160E**102MH20D_CC_1
C811 = DE1B3RA471_GS_1
CN1 = AC-P05CP24_ED
CN6 CN7 = OP-910_GS
CN8 CN9 = 5045-02A_MX
CN10 = A2-2PA-2.54DSA_HR
D1 D2 = TRS8A65F_TS
D3 = GSIB2580_VS
D8 D9 = CRG04_TS_A
D12 D13 D30-D33 = 1SS352_TS_A
D14 D81 = 1SS403E_TS_B
D16 D17 D20 D21 D34 D35 = CMF01_TS_B
D18 D19 = FSU05D60_KC
D22-D29 D84 = TBAT54_TS_B
D36-D47 D51-D58 D83 = CRS01_TS_B
D48 = BAS316_TS_B
D49 = CRZ15_TS_A
D50 = MMSZ4***T*G_OS_A
D80 = CRF03_TS_A
D82 D90-D92 = CMH07_TS_B
F1 = 02150***XEP_LF
F8 = 808****0440_LF
FB1 FB2 = FBMH3216_TY
HS1-HS4 = TP_I_TH2.8_TBLC3.8_ILC0_RC3.9_GS
HS5 HS6 = BPUS15-25_GS
IC1 = HF81GS_MPS
IC2 IC6 IC7 = UCC27524ADR_TI
IC3 = UCC28070APW_TI
IC4 IC5 = UCC27714D_TI
IC8 = LM74700-Q1_TI
IC10 = UCC28950PWR_GS_1
IC11 = TLV70433DBVT_TI
IC13-IC16 = TLP2767_TS
IC20 = ALKG*2**_PN
IC21-IC24 = TC7SZ04FU_TS_1
IC80 = UCC28711D_TI
IC81 = LM317MDCY_TI
L1 L2 = TH23/14V-08231_TP
L3 = NPA080-13x2-20T_GS
L5 L6 = AG1391_GS
L11 L12 = SCF27-10-1300_TN
Q1 Q2 = TK25N60X_TS
Q3-Q6 = TK25N60X5_TS
Q7-Q14 = TPH2900ENH_TS
Q15-Q18 = TPH2R408QM_TS
Q80 = TK12A80W_TS_1
R76 R105 R118 R119 R140 R141 R178 R179 R199-R201 = Chip6432_GS
R77 R78 R106 R107 R128 R129 R800 = MOS3C_KO
R138 = A5MC_UC
RV1 = TND14V-561_CC
T2 T3 = P009-203_PO
T4 = PE-63587NL_PU
T5 T6 = AN0545_GS
T8 = WT2020_GS
TP1-TP12 TP15 TP17-TP22 TP24 TP25 TP28-TP31 TP38 TP39 TP44 TP80-TP82 = HK-2_M8
TP41-TP43 TP45 = LC-22_GS

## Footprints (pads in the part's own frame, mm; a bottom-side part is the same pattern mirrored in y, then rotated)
AC_I_DIA_8_CC_1
  round 1.5 hole 0.85: 1(1.75,0) 2(-1.75,0)
AC_I_DIA_10_CC
  round 1.5 hole 0.85: 1(2.5,0) 2(-2.5,0)
AC_I_DIA_10_CC_2
  round 1.5 hole 0.85: 1(2.5,0) 2(-2.5,0)
AC_I_DIA_10_CC_3
  round 1.5 hole 0.85: 1(2.5,0) 2(-2.5,0)
AC_I_DIA_30_RB
  round 3.5 hole 2: 1(5,0) 2(-5,0)
C_I_890324026034CS_W_1
  round 1.7 hole 1.1: 1(-11.25,0) 2(11.25,0)
C_I_DE1B3RA471_GS_1
  round 1.45 hole 0.85: 1(-3.75,0) 2(3.75,0)
C_I_DE2_KY____M_F_MU
  round 1.45 hole 0.85: 1(-3.75,0) 2(3.75,0)
C_I_DE2_KY____M_F_MU_1
  round 1.45 hole 0.85: 1(-3.75,0) 2(3.75,0)
C_I_LE224_M_OK
  round 1.45 hole 0.85: 1(-6.25,0) 2(6.25,0)
C_I_LE474_M_OK
  round 1.5 hole 0.85: 1(-7.5,0) 2(7.5,0)
C_I_RDER72J104_MU
  round 1.4 hole 0.8: 1(-2.5,0) 2(2.5,0)
CHIP1005_GS_2
  rect 0.45x0.5 smd: 1(-0.475,0) 2(0.475,0)
CHIP1608_GS_1
  rect 0.7x0.8 smd: 1(-0.7,0) 2(0.7,0)
CHIP2012_GS_1
  rect 0.7x1.3 smd: 1(-0.95,0) 2(0.95,0)
CHIP3216_GS_1
  rect 1x1.6 smd: 1(-1.6,0) 2(1.6,0)
CHIP3225_GS_1
  rect 1.1x2.2 smd: 1(-1.65,0) 2(1.65,0)
CHIP6432_GS
  rect 1.7x3.2 smd: 1(-3.15,0) 2(3.15,0)
CN_I_5045_02A_MX
  round 1.8 hole 1.2: 1(1.25,0) 2(-1.25,0)
DI_I_GSIB_5S_4_VS
  round 2.6 hole 1.6: 1(-12.5,0) 2(-2.5,0) 3(5,0) 4(12.5,0)
DI_I_TO220_2_KC
  round 1.8 hole 1.15: A(2.55,0) C(-2.55,0)
DI_I_TO220F_2L_TS
  round 1.8 hole 1.2: A(2.54,0) C(-2.54,0)
DI_S_1SS387_TS_B
  rect 0.8x0.6 smd: A(0,0.85) C(0,-0.85)
DI_S_3_2A1S_2_TS_A
  rect 1.2x1.2 smd: A(-1.4,0) C(1.4,0)
DI_S_3_4E1A_2_TS_B
  rect 1.4x2.1 smd: A(-2.2,0) C(2.2,0)
DI_S_CRS01_TS_B
  rect 1.2x1.2 smd: A(-1.4,0) C(1.4,0)
DI_S_SOD_123_2_OS_A
  rect 0.9x1.2 smd: A(-1.63,0) C(1.63,0)
DI_S_SOT23_3_0_95_TS_1
  rect 0.6x0.7 smd: A(-0.95,-1) C(0,1) NC(0.95,-1)
DI_S_USC_2_TS_B
  rect 0.8x0.9 smd: A(1.175,0) C(-1.15,0)
F_I_808__0440_LF
  round 1.5 hole 0.85: 1(-2.54,0) 2(2.54,0)
F_I_02150__XEP_LF
  round 2.5 hole 1.5: 1(0,0) 2(10,0)
F_I_A5MC_UC
  round 1.5 hole 0.85: 1(-2.75,0)
  round 1.7 hole 1.05: 2(2.75,0)
FB_S_FBMH3216_TY
  rect 1.4x2 smd: 1(-1.8,0) 2(1.8,0)
HP_I_A2_2PA_2_54DSA__1
  round 1.5 hole 0.85: 1(-1.27,0) 2(1.27,0)
HS_I_BPUS15_25_GS
  round 2.8 hole 1.8: 1(0,2.9)
IC_S_SOP_5_0_65_TS_1
  rect 0.4x0.8 smd: 1(-0.65,-0.95) 2(0,-0.95) 3(0.65,-0.95) 4(0.65,0.95) 5(-0.65,0.95)
IC_S_SOP_5_0_95_TI
  rect 0.6x1.05 smd: 1(-0.95,-1.35) 2(0,-1.35) 3(0.95,-1.35) 4(0.95,1.35) 5(-0.95,1.35)
IC_S_SOP_6_0_95_TI
  rect 0.6x1.1 smd: 1(-0.95,-1.3) 2(0,-1.3) 3(0.95,-1.3) 4(0.95,1.3) 5(0,1.3) 6(-0.95,1.3)
IC_S_SOP_7_1_27_TI
  rect 0.6x1.55 smd: CS(1.905,2.7) DRV(0.635,2.7) GND(1.905,-2.7) HV(-1.905,2.7) NTC(0.635,-2.7) VDD(-1.905,-2.7) VS(-0.635,-2.7)
IC_S_SOP_8_1_27_MPS
  rect 0.6x1.6 smd: 1(-1.905,-2.7) 2(-0.635,-2.7) 3(0.635,-2.7) 4(1.905,-2.7) 5(1.905,2.7) 6(0.635,2.7) 7(-0.635,2.7) 8(-1.905,2.7)
IC_S_SOP_8_1_27_TI
  rect 0.6x1.55 smd: 1(-1.905,-2.7) 2(-0.635,-2.7) 3(0.635,-2.7) 4(1.905,-2.7) 5(1.905,2.7) 6(0.635,2.7) 7(-0.635,2.7) 8(-1.905,2.7)
IC_S_SOP_14_1_27_TI
  rect 0.6x1.55 smd: 1(-3.81,-2.7) 2(-2.54,-2.7) 3(-1.27,-2.7) 4(0,-2.7) 5(1.27,-2.7) 6(2.54,-2.7) 7(3.81,-2.7) 8(3.81,2.7) 9(2.54,2.7) 10(1.27,2.7) 11(0,2.7) 12(-1.27,2.7) 13(-2.54,2.7) 14(-3.81,2.7)
IC_S_SOP_20_0_65_TI
  rect 0.3x1.6 smd: 1(-2.925,-2.8) 2(-2.275,-2.8) 3(-1.625,-2.8) 4(-0.975,-2.8) 5(-0.325,-2.8) 6(0.325,-2.8) 7(0.975,-2.8) 8(1.625,-2.8) 9(2.275,-2.8) 10(2.925,-2.8) 11(2.925,2.8) 12(2.275,2.8) 13(1.625,2.8) 14(0.975,2.8) 15(0.325,2.8) 16(-0.325,2.8) 17(-0.975,2.8) 18(-1.625,2.8) 19(-2.275,2.8) 20(-2.925,2.8)
IC_S_SOP_24_0_65_GS__1
  rect 0.4x1.5 smd: 1(-3.575,-2.9) 2(-2.925,-2.9) 3(-2.275,-2.9) 4(-1.625,-2.9) 5(-0.975,-2.9) 6(-0.325,-2.9) 7(0.325,-2.9) 8(0.975,-2.9) 9(1.625,-2.9) 10(2.275,-2.9) 11(2.925,-2.9) 12(3.575,-2.9) 13(3.575,2.9) 14(2.925,2.9) 15(2.275,2.9) 16(1.625,2.9) 17(0.975,2.9) 18(0.325,2.9) 19(-0.325,2.9) 20(-0.975,2.9) 21(-1.625,2.9) 22(-2.275,2.9) 23(-2.925,2.9) 24(-3.575,2.9)
IC_S_SOT223_3_2_3_TI
  rect 0.95x2.15 smd: ADJ(-2.3,0) IN(2.3,0) OUT_0(0,0)
  rect 3.25x2.15 smd: OUT_1(0,5.8)
L_I_AG1391_GS
  oval 7.3x2.5 hole 6.2x1.4: 1(8,-15) 2(-8,15)
L_I_NPA080_13X2_20T__1
  oval 5x3.2 hole 3.5x1.7: 1(0,-5) 2(0,5)
L_I_SCF27_10_1300_TN
  round 2.6 hole 1.6: 1(-12,10) 2(-12,-10) 3(12,-10) 4(12,10)
L_I_TH23_14V_08231_T_1
  round 2.5 hole 1.5: 1(0,-10.5) 2(0,10.5)
PH_S_TLP2767_TS
  rect 0.8x1.3 smd: 1(-1.27,-4.75) 2(0,-4.75) 3(1.27,-4.75) 4(1.27,4.75) 5(0,4.75) 6(-1.27,4.75)
R_I_MOS3C_KO
  round 2 hole 1: 1(0,0) 2(10,0)
RE_I_ALKG_2__PN
  round 1.5 hole 0.9: 1(-10.35,3.75) 2(-10.35,-3.75)
  round 2.2 hole 1.3: 3(6.15,-3.75) 4(9.65,3.75)
T_I_AN0545_GS
  round 6.1 hole 5.1: 1(-17.78,15.24) 3(-17.78,5.08) 4(-17.78,-5.08) 6(-17.78,-15.24) 7(17.78,-15.24) 9(17.78,-5.08) 10(17.78,5.08) 12(17.78,15.24)
  round 2 hole 1: 8(17.78,-10.16) 11(17.78,10.16)
  round 5.3 hole 4.3: 13(25.65,-10.16) 14(25.65,10.16)
T_I_P009_203_PO
  round 1.6 hole 1: 1(-3.6,-3.5) 2(3.6,-3.5)
  round 1.5 hole 0.9: 3(2.575,3.5) 4(-2.575,3.5)
T_I_PE_63587NL_PU
  round 2.6 hole 1.6: 1(-8.89,6.35) 2(-8.89,-6.35) 6(-3.81,6.35) 7(-3.81,-6.35)
  round 1.7 hole 1.1: 3(8.89,6.35) 4(8.89,0) 5(8.89,-6.35)
T_I_WT2020_GS
  round 1.6 hole 1.05: 1(-10.1,10.14) 2(-10.1,6.33) 3(-10.1,2.52) 4(-10.1,-2.52) 5(-10.1,-6.33) 6(-10.1,-10.14) 7(10.1,-10.14) 8(10.1,-7.6) 9(10.1,-5.06) 10(10.1,-2.52) 11(10.1,2.52) 12(10.1,5.06) 13(10.1,7.6) 14(10.1,10.14)
TM_I_AC_P05CP24_ED
  round 2.3 hole 1.65: 1(6.2,-15.8) 2(-0.8,-22.8) 3(-7.8,-15.8)
TM_I_OP_910_GS
  oval 6.8x2.6 hole 5.8x1.6: 1(0,4.5) 2(0,-4.5)
TP_I_LC_22_GS
  round 1.6 hole 1: 1(0,0)
TP_I_TH2_8_TBLC3_8_I_1
  round 3.8 hole 2.8: 1(0,0)
TP_S_HK_2_M8
  rect 3.3x1.7 smd: 1(0,0)
TR_I_TO220SIS_TS_1
  round 1.9 hole 1.3: D(0,-5) G(-2.5,-0.05) S(2.5,0)
TR_I_TO247_3_TS
  round 2.6 hole 1.6: D(0,0) G(-5.44,0) S(5.44,0)
TR_S_SOP_ADVANCE_TS
  rect 0.85x1.45 smd: 1(-1.905,-2.75) 2(-0.635,-2.75) 3(0.635,-2.75) 4(1.905,-2.75) 5(1.905,2.75) 6(0.635,2.75) 7(-0.635,2.75) 8(-1.905,2.75)
unnamed#2
  round 1 smd: (0,0) (2,0)
ZD_I_TND14V_561_CC
  round 1.6 hole 1.05: 1(3.75,-1.3) 2(-3.75,1.3)

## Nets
P48V: C92.2 C93.2 C100.2 CN6.1(TP-1) CN6.2 IC8.4 Q15.5 Q15.6 Q15.7 Q15.8 Q16.5 Q16.6 Q16.7 Q16.8 Q17.5 Q17.6 Q17.7 Q17.8 Q18.5 Q18.6 Q18.7 Q18.8
VCC3R3_1: C95.2 C96.2 C97.2 C98.2 IC21.5 IC22.5 IC23.5 IC24.5 R117.2 R157.1(TP-1) R160.1(TP-1) R163.1(TP-1) R166.1(TP-1) R186.2 R188.2 R190.2 R192.2
VCC12R0_1: C70.2 C806.1(TP-1) D48.C D83.A D84.C IC2.1 IC2.8 IC20.1 IC81.OUT_0 IC81.OUT_1 R83.2 R87.2 R116.1(TP-1) R120.1(TP-1) R121.1(TP-1) R122.1(TP-1) R123.1(TP-1) R810.1(TP-1) TP82.1
VCC12R0_2: C809.2 CN8.1(TP-1) CN9.1(TP-1) D90.C D91.C D92.C R49.1(TP-1) R124.1(TP-1) R125.1(TP-1) R820.2 TP81.1
$BN000001: R90.2 R227.1(TP-1)
$BN000002: R2.2 R228.1(TP-1)
ADJ: C805.1(TP-1) D84.A IC81.ADJ R810.2 R811.1(TP-1)
AUX: C810.2 D81.A R808.2 T8.6
CONN002: C19.1(TP-1) D24.A IC4.11 Q3.S Q4.D R31.1(TP-1) T5.1 T6.1
CONN003: D18.C D19.A L3.2 T5.6 T6.6
CONN004: C2.2 C3.2 C4.2 C5.2 C8.2 C9.2 C59.2 C102.2 IC8.3 IC8.6 L5.2 L6.2 Q15.1 Q15.2 Q15.3 Q16.1 Q16.2 Q16.3 Q17.1 Q17.2 Q17.3 Q18.1 Q18.2 Q18.3 R75.2 R77.1(TP-1) R78.1(TP-1) R106.1(TP-1) R107.2 R128.2 R129.1(TP-1) R199.2 R200.2 R201.2 TP31.1
CS: D14.C R67.2 R185.2
CSA: D13.C D33.C R7.2 R87.1(TP-1) R170.1(TP-1) TP2.1
CSB: D12.C D31.C R8.2 R83.1(TP-1) R169.1(TP-1) TP1.1
FG1: CN1.2
FG2: C79.1(TP-1)
FG3: C32.1(TP-1) C64.1(TP-1) C78.1(TP-1)
FG4: C31.1(TP-1) C63.1(TP-1)
FG5: C101.2 R805.2
FG6: C93.1(TP-1) C94.2 R205.1(TP-1) R206.1(TP-1)
FG7: R204.1(TP-1)
GDA: C81.2 IC2.2 IC3.14 TP5.1
GDB: C80.2 IC2.4 IC3.17 TP6.1
HS1_1: R224.2
HS1_2: R225.2
IN: C804.2 C808.1(TP-1) D82.C D83.C IC81.IN
LGND: C2.1(TP-1) C3.1(TP-1) C4.1(TP-1) C5.1(TP-1) C8.1(TP-1) C9.1(TP-1) C23.1(TP-1) C24.1(TP-1) C25.1(TP-1) C26.1(TP-1) C27.1(TP-1) C51.1(TP-1) C60.1(TP-1) C61.1(TP-1) C68.1(TP-1) C69.1(TP-1) C88.1(TP-1) C89.1(TP-1) C90.1(TP-1) C91.1(TP-1) C92.1(TP-1) C94.1(TP-1) C99.1(TP-1) C100.1(TP-1) C102.1(TP-1) C809.1(TP-1) C811.1(TP-1) CN7.1(TP-1) CN7.2 CN8.2 CN9.2 CN10.2 D26.A D27.A D28.A D29.A IC6.3 IC7.3 IC8.2 IC10.24 Q7.1 Q7.2 Q7.3 Q8.1 Q8.2 Q8.3 Q9.1 Q9.2 Q9.3 Q10.1 Q10.2 Q10.3 Q11.1 Q11.2 Q11.3 Q12.1 Q12.2 Q12.3 Q13.1 Q13.2 Q13.3 Q14.1 Q14.2 Q14.3 R9.1(TP-1) R19.1(TP-1) R21.1(TP-1) R22.1(TP-1) R25.1(TP-1) R43.1(TP-1) R45.1(TP-1) R48.1(TP-1) R50.1(TP-1) R51.1(TP-1) R52.1(TP-1) R53.1(TP-1) R54.1(TP-1) R55.1(TP-1) R56.1(TP-1) R61.1(TP-1) R64.1(TP-1) R66.1(TP-1) R70.1(TP-1) R76.1(TP-1) R105.1(TP-1) R118.1(TP-1) R119.1(TP-1) R140.1(TP-1) R141.1(TP-1) R180.1(TP-1) R181.1(TP-1) R182.1(TP-1) R184.1(TP-1) R185.1(TP-1) R194.2 R195.2 R196.2 R197.2 R199.1(TP-1) R200.1(TP-1) R201.1(TP-1) R204.2 R205.2 R206.2 R208.1(TP-1) R209.1(TP-1) R805.1(TP-1) R820.1(TP-1) T4.3 T8.8 T8.9 TP41.1 TP42.1
OUTA1: IC21.4 R111.1(TP-1) R187.2
OUTA2: IC10.22 R149.2
OUTB1: IC22.4 R110.1(TP-1) R189.2
OUTB2: IC10.21 R150.2
OUTC1: IC23.4 R113.1(TP-1) R191.2
OUTC2: IC10.20 R151.2
OUTD1: IC24.4 R112.1(TP-1) R193.2
OUTD2: IC10.19 R152.2
OUTE: IC6.2 IC7.2 IC10.18 TP25.1
OUTF: IC6.4 IC7.4 IC10.17 TP24.1
PFC_OUT: C1.2 C7.2 D1.C D2.C D3.1 F8.1(TP-1) R92.2 R178.2 T4.2 TP44.1
PFC_VIN: D8.C D9.C R95.2
PN: C1.1(TP-1) C7.1(TP-1) C34.1(TP-1) C35.1(TP-1) C36.1(TP-1) C37.1(TP-1) C38.1(TP-1) C39.1(TP-1) C40.1(TP-1) C42.1(TP-1) C43.1(TP-1) C45.1(TP-1) C47.1(TP-1) C48.1(TP-1) C49.1(TP-1) C50.1(TP-1) C53.1(TP-1) C54.1(TP-1) C55.1(TP-1) C56.1(TP-1) C57.1(TP-1) C58.1(TP-1) C62.1(TP-1) C66.1(TP-1) C67.1(TP-1) C70.1(TP-1) C71.1(TP-1) C72.1(TP-1) C73.1(TP-1) C74.1(TP-1) C75.1(TP-1) C76.1(TP-1) C77.1(TP-1) C80.1(TP-1) C81.1(TP-1) C82.1(TP-1) C83.1(TP-1) C84.1(TP-1) C85.1(TP-1) C86.1(TP-1) C87.1(TP-1) C95.1(TP-1) C96.1(TP-1) C97.1(TP-1) C98.1(TP-1) C101.1(TP-1) C103.1(TP-1) C800.1(TP-1) C802.1(TP-1) C803.1(TP-1) C804.1(TP-1) C805.2 C806.2 C808.2 C811.2 C812.1(TP-1) D3.4 D18.A D22.A D25.A D49.A D50.C HS5.1 HS6.1 IC2.3 IC3.16 IC4.3 IC4.5 IC5.3 IC5.5 IC11.1 IC13.4 IC14.4 IC15.4 IC16.4 IC20.2 IC21.3 IC22.3 IC23.3 IC24.3 IC80.GND Q1.S Q2.S Q4.S Q6.S R2.1(TP-1) R7.1(TP-1) R8.1(TP-1) R29.1(TP-1) R33.1(TP-1) R71.1(TP-1) R73.1(TP-1) R90.1(TP-1) R93.1(TP-1) R96.1(TP-1) R98.1(TP-1) R99.1(TP-1) R100.1(TP-1) R101.1(TP-1) R102.1(TP-1) R103.1(TP-1) R104.1(TP-1) R174.1(TP-1) R175.1(TP-1) R176.1(TP-1) R179.1(TP-1) R187.1(TP-1) R189.1(TP-1) R191.1(TP-1) R193.1(TP-1) R198.1(TP-1) R220.1(TP-1) R221.1(TP-1) R222.1(TP-1) R223.1(TP-1) R224.1(TP-1) R225.1(TP-1) R801.2 R807.1(TP-1) R809.1(TP-1) R811.2 R812.1(TP-1) R813.1(TP-1) R814.1(TP-1) T2.2 T3.2 T8.4 TP43.1 TP45.1
SIG1: C30.2 C78.2 F1.2 L11.2 R79.2 RV1.1(TP-1)
SIG2: C30.1(TP-1) C79.2 CN1.3 L11.3 R80.1(TP-1) RV1.2
SIG6: C33.1(TP-1) C63.2 C65.1(TP-1) D3.3 D9.A L2.1(TP-1) L12.4
SIG8: C33.2 C65.2 D3.2 D8.A IC20.3 L1.1(TP-1) R138.2
SIG9: IC1.2 IC1.3 R79.1(TP-1)
SIG10: IC1.6 IC1.7 R80.2
SIG11: D2.A L2.2 T2.4
SIG12: D1.A L1.2 T3.4
SIG15: D12.A R81.2 T2.1
SIG16: C34.2 R81.1(TP-1)
SIG18: Q2.D T2.3
SIG20: D13.A R85.2 T3.1
SIG21: C36.2 R85.1(TP-1)
SIG22: Q1.D T3.3
SIG23: FB1.1(TP-1) R71.2 R72.2 R108.2
SIG24: C35.2 D31.A R82.2 R172.2
SIG25: C37.2 D33.A R86.2 R173.2
SIG27: FB2.1(TP-1) R73.2 R74.2 R109.2
SIG30: D32.C D38.A D39.C IC2.7 R86.1(TP-1)
SIG39: R89.2 R91.1(TP-1)
SIG40: R91.2 R92.1(TP-1)
SIG43: C45.2 C46.2 IC3.11
SIG44: C46.1(TP-1) R99.2
SIG45: C43.2 C44.2 IC3.12
SIG46: C44.1(TP-1) R98.2
SIG47: C40.2 C41.2 IC3.3
SIG48: C41.1(TP-1) R93.2
SIG49: C39.2 IC3.4 R89.1(TP-1) R227.2 TP8.1
SIG50: C49.2 IC3.18
SIG51: C50.2 IC3.1 R171.1(TP-1)
SIG52: IC3.19 R100.2 R198.2
SIG53: IC3.7 R101.2 R176.2
SIG54: IC3.6 R102.2 R175.2
SIG55: IC3.20 R103.2 R174.2
SIG56: IC3.2 R104.2
SIG60: R94.2 R95.1(TP-1)
SIG61: R1.2 R94.1(TP-1)
SIG62: C38.2 IC3.5 R1.1(TP-1) R228.2 TP7.1
SIG65: C19.2 D17.C IC4.13
SIG75: C18.2 D16.C IC5.13
SIG82: Q6.G R29.2 R136.2 R137.2
SIG86: C47.2 C48.2 D49.C IC3.15 R120.2
SIG89: C54.2 IC5.1 R111.2 TP38.1
SIG90: C53.2 IC5.2 R110.2 TP39.1
SIG91: C58.2 C84.2 C85.2 IC4.7 R115.1(TP-1) R122.2
SIG92: D17.A R115.2
SIG93: C57.2 IC4.1 R113.2 TP9.1
SIG94: C56.2 IC4.2 R112.2 TP10.1
SIG95: D16.A R114.2
SIG100: D36.C R72.1(TP-1)
SIG101: D37.A R108.1(TP-1)
SIG102: D30.C D36.A D37.C IC2.5 R82.1(TP-1)
SIG104: C62.2 C82.2 C83.2 IC2.6 R121.2
SIG105: D39.A R109.1(TP-1)
SIG106: D38.C R74.1(TP-1)
SIG115: C106.2 D34.A Q9.5 Q9.6 Q9.7 Q9.8 Q10.5 Q10.6 Q10.7 Q10.8 T5.14
SIG116: D29.C D57.A D58.C IC7.7
SIG117: D28.C D55.A D56.C IC7.5
SIG118: Q9.4 Q10.4 R24.2 R25.2 R215.2 TP20.1
SIG121: C60.2 C90.2 C91.2 IC7.6 R124.2
SIG122: C59.1(TP-1) IC8.1
SIG124: C61.2 C88.2 C89.2 IC6.6 R125.2
SIG126: D26.C D53.A D54.C IC6.7
SIG127: D27.C D51.A D52.C IC6.5
SIG128: Q13.4 Q14.4 R20.2 R21.2 R213.2 TP19.1
SIG135: C105.2 D21.A Q11.5 Q11.6 Q11.7 Q11.8 Q12.5 Q12.6 Q12.7 Q12.8 T6.10 T6.11 T6.12 TP30.1
SIG136: IC8.5 R6.1(TP-1)
SIG148: IC10.6 R51.2 R180.2
SIG149: IC10.7 R52.2 R181.2
SIG150: IC10.8 R53.2 R182.2
SIG151: IC10.9 R54.2
SIG152: C25.2 CN10.1(TP-1) IC10.5 R50.2
SIG154: IC10.2 R44.1(TP-1) R45.2
SIG156: C20.1(TP-1) C22.1(TP-1) IC10.3 R42.1(TP-1) R43.2 R47.2
SIG157: R42.2 R46.2 R75.1(TP-1)
SIG167: C21.1(TP-1) R47.1(TP-1)
SIG168: C21.2 C22.2 IC10.4 R48.2
SIG170: C20.2 R46.1(TP-1)
SIG171: IC10.14 R65.1(TP-1) R66.2 R209.2 R211.1(TP-1)
SIG172: IC10.13 R63.1(TP-1) R64.2 R208.2 R210.1(TP-1)
SIG173: C26.2 IC10.15 R63.2 R65.2 R69.1(TP-1) R70.2
SIG174: R59.2 R67.1(TP-1) R69.2
SIG175: R59.1(TP-1) R60.2 R62.1(TP-1)
SIG177: IC10.12 R60.1(TP-1) R61.2 R184.2
SIG179: IC10.10 R55.2 R57.1(TP-1) R207.1(TP-1)
SIG181: IC10.11 R56.2 R58.1(TP-1)
SIG183: C23.2 C24.2 IC10.23 R49.2
SIG185: C67.2 IC11.3 R117.1(TP-1)
SIG193: CN1.1 F1.1(TP-1)
SIG199: C32.2 C52.2 L11.1 L12.2
SIG200: C31.2 C52.1(TP-1) L11.4 L12.3
SIG205: Q4.G R33.2 R134.2 R135.2 TP12.1
SIG206: Q3.G R31.2 R126.2 R127.2 TP11.1
SIG223: C66.2 IC11.2 R130.2
SIG228: IC13.5 R153.2
SIG229: C71.2 IC13.6 R157.2
SIG230: IC13.1 R149.1(TP-1)
SIG231: C72.2 IC14.6 R160.2
SIG234: IC14.5 R154.2
SIG236: IC14.1 R150.1(TP-1)
SIG237: C73.2 IC15.6 R163.2
SIG242: IC15.5 R155.2
SIG243: IC16.1 R152.1(TP-1)
SIG245: IC16.5 R156.2
SIG246: C74.2 IC16.6 R166.2
SIG247: IC15.1 R151.1(TP-1)
SIG249: C18.1(TP-1) D23.A IC5.11 L3.1(TP-1) Q5.S Q6.D R28.1(TP-1) TP15.1
SIGN254: D30.A R172.1(TP-1)
SIGN255: D32.A R173.1(TP-1)
SIGN256: C77.2 IC3.10 R96.2 R97.1(TP-1) R177.1(TP-1)
SIGN260: C76.2 IC3.9 R170.2
SIGN262: C75.2 IC3.8 R169.2
SIGN266: FB1.2 Q2.G TP3.1
SIGN267: FB2.2 Q1.G TP4.1
SIGN269: D23.C D42.A D43.C IC5.12
SIGN270: C55.2 C86.2 C87.2 IC5.7 R114.1(TP-1) R123.2
SIGN271: R178.1(TP-1) R179.2
SIGN275: D48.A D50.A
SIGN284: IC13.3 R194.1(TP-1)
SIGN287: IC14.3 R195.1(TP-1)
SIGN289: IC16.3 R197.1(TP-1)
SIGN291: IC15.3 R196.1(TP-1)
SIGN304: IC21.2 R153.1(TP-1) R186.1(TP-1)
SIGN305: IC22.2 R154.1(TP-1) R188.1(TP-1)
SIGN314: IC23.2 R155.1(TP-1) R190.1(TP-1)
SIGN315: IC24.2 R156.1(TP-1) R192.1(TP-1)
SIGN318: D24.C D40.A D41.C IC4.12
SIGN322: D22.C D46.A D47.C IC5.6
SIGN325: D25.C D44.A D45.C IC4.6
SIGN336: D53.C R20.1(TP-1)
SIGN337: D54.A R213.1(TP-1)
SIGN338: D51.C R18.1(TP-1)
SIGN339: D52.A R212.1(TP-1)
SIGN341: D57.C R24.1(TP-1)
SIGN342: D58.A R215.1(TP-1)
SIGN343: Q7.4 Q8.4 R22.2 R23.2 R214.2 TP22.1
SIGN344: D55.C R23.1(TP-1)
SIGN345: D56.A R214.1(TP-1)
SIGN355: C103.2 D19.C Q3.D Q5.D T4.1
SIGN356: D14.A R9.2 T4.5
SIGN360: L5.1(TP-1) T5.7 T5.8 T5.9 T5.13 TP18.1
SIGN364: C64.2 IC20.4 L12.1 R138.1(TP-1)
SIGN366: HS1.1 R220.2
SIGN369: HS2.1 R221.2
SIGN371: HS3.1 R222.2
SIGN373: HS4.1 R223.2
VREF: C99.2 IC10.1 R44.2 R57.2 R58.2 R62.2 R207.2 R210.2 R211.2
VREF_PFC: C42.2 IC3.13 R97.2 R171.2 R177.2
N03591: R116.2 R130.1(TP-1)
N05004: Q5.G R28.2 R132.2 R133.2
N07003: L6.1(TP-1) T6.7 T6.8 T6.9 T6.13 TP17.1
N07083: C51.2 C69.2 D34.C D35.C R105.2 R106.2 R107.1(TP-1) R129.2
N07119: C27.2 C68.2 D20.C D21.C R76.2 R77.2 R78.2 R128.1(TP-1)
N07203: Q11.4 Q12.4 R18.2 R19.2 R212.2 TP21.1
N07369: C104.2 D20.A Q13.5 Q13.6 Q13.7 Q13.8 Q14.5 Q14.6 Q14.7 Q14.8 T6.14 TP29.1
N07429: C107.2 D35.A Q7.5 Q7.6 Q7.7 Q7.8 Q8.5 Q8.6 Q8.7 Q8.8 T5.10 T5.11 T5.12
N11927: Q15.4 Q16.4 Q17.4 Q18.4 R6.2 TP28.1
N043041: D40.C R126.1(TP-1)
N043160: D41.A R127.1(TP-1)
N043261: D44.C R134.1(TP-1)
N043380: D45.A R135.1(TP-1)
N043481: D42.C R132.1(TP-1)
N043600: D43.A R133.1(TP-1)
N043701: D46.C R136.1(TP-1)
N043820: D47.A R137.1(TP-1)
N66342: D80.A Q80.D T8.3 TP80.1
N66362: Q80.S R803.1(TP-1) R804.2 R812.2 R813.2 R814.2
N14550647: C812.2 IC80.VS R808.1(TP-1) R809.2
N14553110: D90.A D91.A D92.A T8.12 T8.13
N14557584: C800.2 C801.1(TP-1) C807.1(TP-1) F8.2 IC80.HV R800.2 T8.1
N14557651: D81.C R806.1(TP-1)
N14557692: C802.2 IC80.VDD R806.2
N14557973: IC80.NTC R807.2
N14565222: IC80.DRV R802.1(TP-1)
N14565783: C803.2 IC80.CS R804.1(TP-1)
N14565980: D82.A T8.5
N16776505: Q80.G R802.2 R803.2
N16785059: C801.2 C807.2 D80.C R800.1(TP-1)
N16790081: C810.1(TP-1) R801.1(TP-1)
N16975142: T6.3 T6.4
N16985418: T5.3 T5.4
N17045135: C104.1(TP-1) R118.2
N17045143: C107.1(TP-1) R141.2
N17045153: C106.1(TP-1) R140.2
N17045822: C105.1(TP-1) R119.2

Pads without a net: D22 NC; D23 NC; D24 NC; D25 NC; D26 NC; D27 NC; D28 NC; D29 NC; D84 NC; IC1 1 4 5 8; IC4 4 8 9 10 14; IC5 4 8 9 10 14; IC6 1 8; IC7 1 8; IC10 16; IC11 4 5; IC13 2; IC14 2; IC15 2; IC16 2; IC21 1; IC22 1; IC23 1; IC24 1; T4 4 6 7; T8 2 7 10 11 14

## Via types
v1: diameter 0.6, hole 0.3, TOP to BOTTOM, 1184 vias
v2: diameter 7, hole 3.2, TOP to BOTTOM, 8 vias

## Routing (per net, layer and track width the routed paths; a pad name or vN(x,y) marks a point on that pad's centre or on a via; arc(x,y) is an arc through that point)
P48V: length 12
  BOTTOM w0.6: IC8.4 C100.2
  BOTTOM w1: 288.55,33.25 288.55,36.55 290.25,38.25 294.75,38.25
  vias: v1(300.95,50.6) v1(300.95,49.4) v1(300.95,48.2) v1(300.95,47) v1(301.55,50) v1(301.55,48.8) v1(301.55,47.6) v1(301.55,46.4) v1(302.15,50.6) v1(302.15,49.4) v1(302.15,48.2) v1(302.15,47) v1(302.75,50) v1(302.75,48.8) v1(302.75,47.6) v1(302.75,46.4) v1(303.35,50.6) v1(303.35,49.4) v1(303.35,48.2) v1(303.35,47) v1(303.95,50) v1(303.95,48.8) v1(303.95,47.6) v1(303.95,46.4) v1(304.55,50.6) v1(304.55,49.4) v1(304.55,48.2) v1(304.55,47) v1(305.15,50) v1(305.15,48.8) v1(305.15,47.6) v1(305.15,46.4) v1(305.75,50.6) v1(305.75,49.4) v1(305.75,48.2) v1(305.75,47) v1(306.35,50) v1(306.35,48.8) v1(306.35,47.6) v1(306.35,46.4) v1(306.95,50.6) v1(306.95,49.4) v1(306.95,48.2) v1(306.95,47) v1(307.55,50) v1(307.55,48.8) v1(307.55,47.6) v1(307.55,46.4) v1(308.15,50.6) v1(308.15,49.4) v1(308.15,48.2) v1(308.15,47) v1(308.75,50) v1(308.75,48.8) v1(308.75,47.6) v1(308.75,46.4) v1(309.35,50.6) v1(309.35,49.4) v1(309.35,48.2) v1(309.35,47) v1(309.95,50) v1(309.95,48.8) v1(309.95,47.6) v1(309.95,46.4)
VCC3R3_1: length 108.4
  TOP w0.4: IC24.5 226.25,15.75 226.18,15.82 225.6,15.82 ; 227.1,19.95 IC23.5 225.6,19.95
  TOP w0.45: v1(224.7,20.3) 225.07,19.93 C97.2 ; 225.6,15.82 225.12,15.82 v1(224.7,16.25)
  TOP w0.5: R163.1 231.8,20 231.4,19.6 R190.2 230.5,18.35 v1(230.6,18.25)
  TOP w0.6: v1(230.5,14.95) R192.2 231.35,15.8 231.65,16.1 R166.1 ; v1(176.35,35.45) v1(175.5,35.45)
  CONDUCTIVE3 w0.8: v1(175.5,35.45) v1(176.35,35.45) 191.3,35.45 196.5,30.25 196.5,28.45 198.8,26.15 198.8,23.75 205.2,17.35 v1(221.45,17.35)
  CONDUCTIVE4 w0.5: 230.6,20.8 v1(230.6,23) ; 230.6,20.8 230.1,20.3 230.6,19.8 ; 230.6,20.8 230.6,19.8 ; 227.85,17.35 226.75,16.25 v1(224.7,16.25) ; 230.6,19.8 v1(230.6,18.25) 230.6,15.05 v1(230.5,14.95)
  CONDUCTIVE4 w0.8: 227.85,19.5 228.65,20.3 ; 227.85,19.5 227.85,17.35 ; 227.85,19.5 227.05,20.3 ; 228.65,20.3 227.05,20.3 ; 228.65,20.3 230.1,20.3 ; v1(221.45,17.35) 221.45,18.55 223.2,20.3 v1(224.7,20.3) 227.05,20.3
  BOTTOM w0.45: IC22.5 226.4,17.15 226.03,16.77 C96.2 225.22,16.77 v1(224.7,16.25) ; IC21.5 226.4,21.45 225.97,21.02 225.03,21.02 224.7,20.7 v1(224.7,20.3)
  BOTTOM w0.5: 231.8,17.35 R188.2 230.5,18.15 v1(230.6,18.25) ; R157.1 231.05,21.8 230.85,22 R186.2 230.5,22.9 v1(230.6,23)
  BOTTOM w0.8: R117.2 176.9,35.45 v1(176.35,35.45) v1(175.5,35.45)
VCC12R0_1: length 316.6
  TOP w0.3: v1(88.8,77.2) 88.8,76.6 ; IC20.1 91.95,71.8 90.35,73.4 90.35,75.45 89.35,76.45 88.8,76.45 ; 139.04,50.05 139.04,50.5 139.44,50.9 v1(143,50.9) ; D48.C 87.9,76.45 88.63,76.45
  TOP w0.4: 88.8,76.6 C70.2 88.8,76.45 88.63,76.45
  TOP w0.5: 139.04,41.8 137.5,41.8 R87.2 ; 139.04,41.8 IC2.1 ; 139.04,41.8 140.25,40.6 141.95,40.6 143,39.55 v1(143,38.9) ; D84.C 190.77,39.05 189.77,40.05 189.3,40.05 D83.A 188.45,40.9 R810.1 IC81.OUT_0 ; v1(146.15,40.7) 146.5,40.35 147.25,40.35
  TOP w0.6: 149.05,94.95 R123.1 145.45,94.95 144.45,93.95 v1(144.45,93.3) v1(144.45,92.05) ; 139.04,50.05 IC2.8 ; 177.75,62.75 177.75,60.25 176.6,59.1 v1(174.05,59.1) v1(172.8,59.1) ; v1(125.5,2) R120.1 ; 174.85,40.6 174.99,40.74 176.85,40.74
  TOP w0.7: v1(146.15,40.7) R121.1
  TOP w0.95: 185.05,40.9 IC81.OUT_1 179.25,40.9
  TOP w1: 179.25,40.9 179.25,39.9 181.4,37.75 C806.1 179.15,36.2 176.85,38.5 176.85,41.35
  CONDUCTIVE4 w2: v1(88.8,77.2) 91.25,77.2 106,62.45 106,51.4 112.2,45.2 123.5,45.2 127.8,49.5 140.25,49.5 ; 141.35,48.4 141.35,44.15 144.8,40.7 ; 141.35,48.4 140.25,49.5 ; 141.35,48.4 141.35,49.5 ; v1(125.5,2) 140.25,16.75 140.25,36.15 v1(143,38.9) 144.8,40.7 ; 143.62,90.67 143.1,90.15 143.1,78.75 146.25,75.6 166.2,75.6 175.25,66.55 175.25,60.3 v1(174.05,59.1) 174.05,51.8 176.45,49.4 176.45,41.75 ; 140.25,49.5 141.35,49.5 ; 141.35,49.5 141.55,49.5 142.95,50.9 ; 144.8,40.7 v1(146.15,40.7) 161.2,40.7 161.95,41.45 176.35,41.45
  BOTTOM w0.6: v1(144.45,92.05) v1(144.45,93.3) ; v1(174.05,59.1) v1(172.8,59.1)
  vias: v1(176.35,41.75) v1(176.35,40.85) v1(177.25,41.75) v1(177.25,40.85)
VCC12R0_2: length 167.9
  TOP w0.6: v1(252.1,57.5) v1(252.95,57.5) R124.1 ; R125.1 v1(252.95,95.6) v1(252.1,95.6) ; v1(251.2,23.1) v1(251.2,24)
  TOP w1: v1(274.75,13.2) TP81.1
  CONDUCTIVE3 w1: v1(251.2,23.1) v1(251.2,24) 251.2,27.75 252.1,28.65 252.1,56.65 ; v1(252.1,57.5) 252.1,58.35 ; v1(252.1,57.5) v1(252.95,57.5) ; v1(252.1,57.5) 252.1,56.65 ; 252.1,58.35 252.1,94.75 ; 252.1,58.35 v1(252.95,57.5) ; v1(252.95,57.5) 252.1,56.65 ; 252.1,94.75 v1(252.95,95.6) v1(252.1,95.6) 252.1,94.75
  BOTTOM w0.6: v1(252.95,95.6) v1(252.1,95.6) ; R49.1 v1(251.2,23.1) ; v1(252.95,57.5) v1(252.1,57.5)
  BOTTOM w1: 267.25,8.25 269.8,8.25 v1(274.75,13.2) 276.3,13.2 279.5,16.4 279.5,22.9 276.1,26.3 253.5,26.3 v1(251.2,24) v1(251.2,23.1)
  BOTTOM w1.8: CN8.1 258.25,8.25 ; CN9.1 267.25,8.25
  BOTTOM w2: 267.25,8.25 C809.2
$BN000001: length 1.2
  BOTTOM w0.4: R227.1 R90.2
$BN000002: length 1.4
  BOTTOM w0.4: R2.2 152.25,7.25 R228.1
ADJ: length 6.9
  TOP w0.4: R810.2 R811.1 187.2,38.2 ; 187.2,38.2 187,38.4 185.3,38.4 IC81.ADJ ; 187.2,38.2 187.28,38.12 C805.1 ; 188.5,38.15 C805.1 ; C805.1 188.5,38.1 189.05,38.1 189.85,37.3 D84.A
AUX: length 32.6
  CONDUCTIVE4 w1.6: T8.6 193.95,27.66 193.95,37.4 190,41.35 185.85,41.35 v1(181.1,46.1)
  BOTTOM w0.6: R808.2 181.75,46.75 v1(181.1,46.1) D81.A
CONN002: length 35.1
  TOP w0.6: 166.1,69.9 166.1,68.45 v1(165.3,67.65) ; 148.5,78.6 147.9,79.2 ; 148.5,78.6 148.5,76.05 150.05,74.5 R31.1 D24.A 154.5,71.85 v1(154.5,70.4) ; 148.5,78.6 149.1,79.2 ; 148.5,78.6 Q3.S
  CONDUCTIVE4 w0.6: v1(154.5,70.4) 155.85,71.75 163.25,71.75 165.3,69.7 v1(165.3,67.65)
  BOTTOM w0.45: C19.1 165.3,67.28 v1(165.3,67.65)
CONN003: length 33.7
  BOTTOM w3.2: 175.8,99.3 L3.2 175.8,101.9 177.9,104 193.35,104
  BOTTOM w3.5: 190.9,92.5 193.35,94.95 193.35,104 193.25,103.9
  vias: v1(189.5,81.5) v1(189.5,80.6) v1(189.5,79.7) v1(189.5,78.8) v1(189.5,77.9) v1(190.4,81.5) v1(190.4,80.6) v1(190.4,79.7) v1(190.4,78.8) v1(190.4,77.9) v1(191.3,81.5) v1(191.3,80.6) v1(191.3,79.7) v1(191.3,78.8) v1(191.3,77.9) v1(192.2,81.5) v1(192.2,80.6) v1(192.2,79.7) v1(192.2,78.8) v1(192.2,77.9) v1(193.1,80.6) v1(193.1,79.7) v1(193.1,78.8) v1(193.1,77.9) v1(194,79.7) v1(194,78.8) v1(194,77.9)
CONN004: length 123.1
  TOP w1: C3.2 308.5,93.5 ; C3.2 308.5,90.5 ; C3.2 307,92 ; C8.2 294,116.2 ; C8.2 292.5,114.7 ; C8.2 291,116.2 ; C4.2 307,80 ; C4.2 308.5,81.5 ; C4.2 308.5,78.5 ; C5.2 308.5,66.5 ; C5.2 308.5,69.5 ; C5.2 307,68 ; C2.2 307,104 ; C2.2 308.5,105.5 ; C2.2 308.5,102.5 ; C9.2 306,115 ; C9.2 303,115 ; C9.2 304.5,113.5
  CONDUCTIVE2 w0.3: v1(296.25,60.2) v1(295.65,60.8)
  CONDUCTIVE4 w1: v1(273.15,23.85) 273.15,28.15 277.8,32.8 291.6,32.8 292.4,33.6 v1(292.4,34.2) 291.35,35.25 290.95,35.25 288.45,37.75 288.45,56.2 292.65,60.4 295.52,60.4
  BOTTOM w0.3: 290.3,30.95 290.3,31.4 290.7,31.8 291.8,31.8 292.2,32.2 292.2,32.85
  BOTTOM w0.4: C59.2 293.7,33.4 292.9,34.2 v1(292.4,34.2)
  BOTTOM w0.6: v1(292.4,34.2) 292.4,33.95 292.2,33.75 IC8.6 292.2,32.85 ; v1(273.15,23.85) R75.2 ; 290.3,30.95 IC8.3
  BOTTOM w1: C8.2 294,116.2 ; C8.2 291,116.2 ; C8.2 292.5,114.7 ; C3.2 308.5,90.5 ; C3.2 308.5,93.5 ; C3.2 307,92 ; C5.2 307,68 ; C5.2 308.5,69.5 ; C5.2 308.5,66.5 ; C9.2 306,115 ; C9.2 304.5,113.5 ; C9.2 303,115 ; C2.2 307,104 ; C2.2 308.5,102.5 ; C2.2 308.5,105.5 ; C4.2 308.5,78.5 ; C4.2 307,80 ; C4.2 308.5,81.5
  vias: v1(295.65,66.8) v1(295.65,65.6) v1(295.65,64.4) v1(295.65,63.2) v1(295.65,62) v1(296.25,66.2) v1(296.25,65) v1(296.25,63.8) v1(296.25,62.6) v1(296.25,61.4) v1(296.85,66.8) v1(296.85,65.6) v1(296.85,64.4) v1(296.85,63.2) v1(296.85,62) v1(296.85,60.8) v1(297.45,66.2) v1(297.45,65) v1(297.45,63.8) v1(297.45,62.6) v1(297.45,61.4) v1(297.45,60.2) v1(298.05,66.8) v1(298.05,65.6) v1(298.05,64.4) v1(298.05,63.2) v1(298.05,62) v1(298.05,60.8) v1(298.65,66.2) v1(298.65,65) v1(298.65,63.8) v1(298.65,62.6) v1(298.65,61.4) v1(298.65,60.2) v1(299.25,66.8) v1(299.25,65.6) v1(299.25,64.4) v1(299.25,63.2) v1(299.25,62) v1(299.25,60.8) v1(299.85,66.2) v1(299.85,65) v1(299.85,63.8) v1(299.85,62.6) v1(299.85,61.4) v1(299.85,60.2) v1(300.45,66.8) v1(300.45,65.6) v1(300.45,64.4) v1(300.45,63.2) v1(300.45,62) v1(300.45,60.8) v1(301.05,66.2) v1(301.05,65) v1(301.05,63.8) v1(301.05,62.6) v1(301.05,61.4) v1(301.05,60.2) v1(301.65,66.8) v1(301.65,65.6) v1(301.65,64.4) v1(301.65,63.2) v1(301.65,62) v1(301.65,60.8) v1(302.25,66.2) v1(302.25,65) v1(302.25,63.8) v1(302.25,62.6) v1(302.25,61.4) v1(302.25,60.2)
